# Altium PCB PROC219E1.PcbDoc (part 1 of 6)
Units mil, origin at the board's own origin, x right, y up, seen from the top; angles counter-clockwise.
Board outline 5354.33 x 5354.33 mil, 4 copper layers (Top Layer, Inner Layer 1, Inner Layer 2, Bottom Layer), stack 62.449 mil thick; 579 components, 299 nets, 1709 pads, 802 vias.
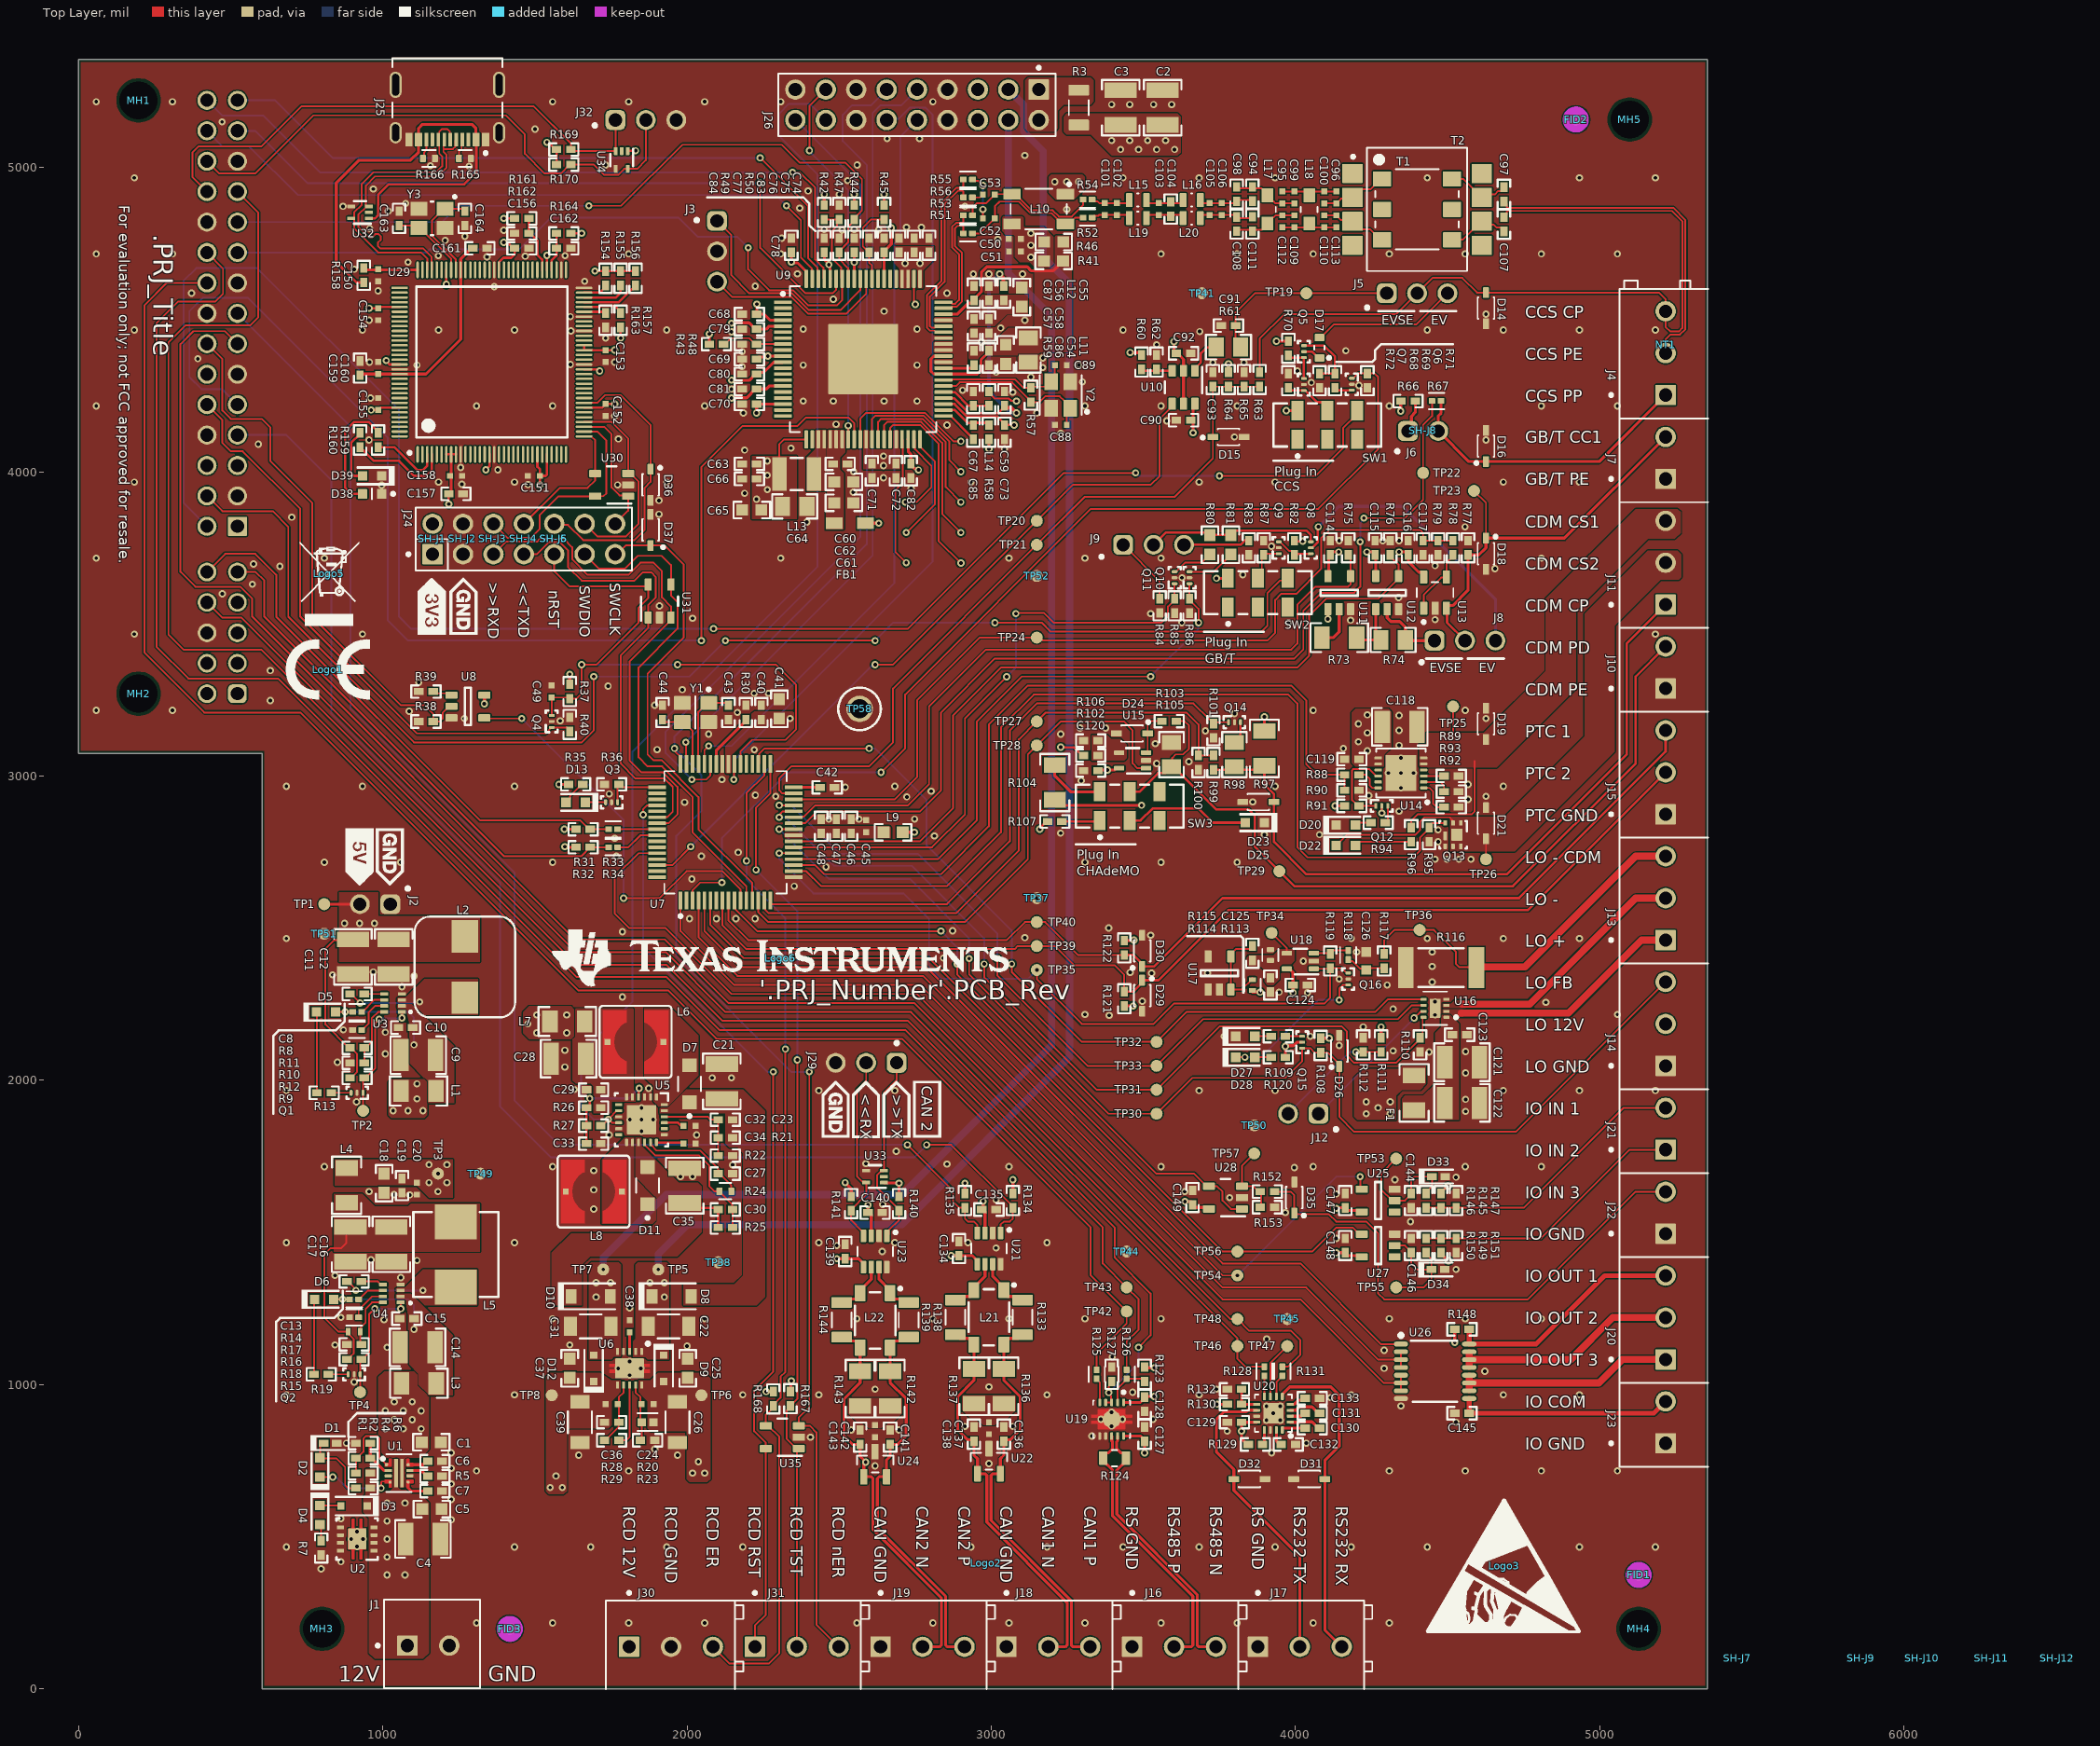
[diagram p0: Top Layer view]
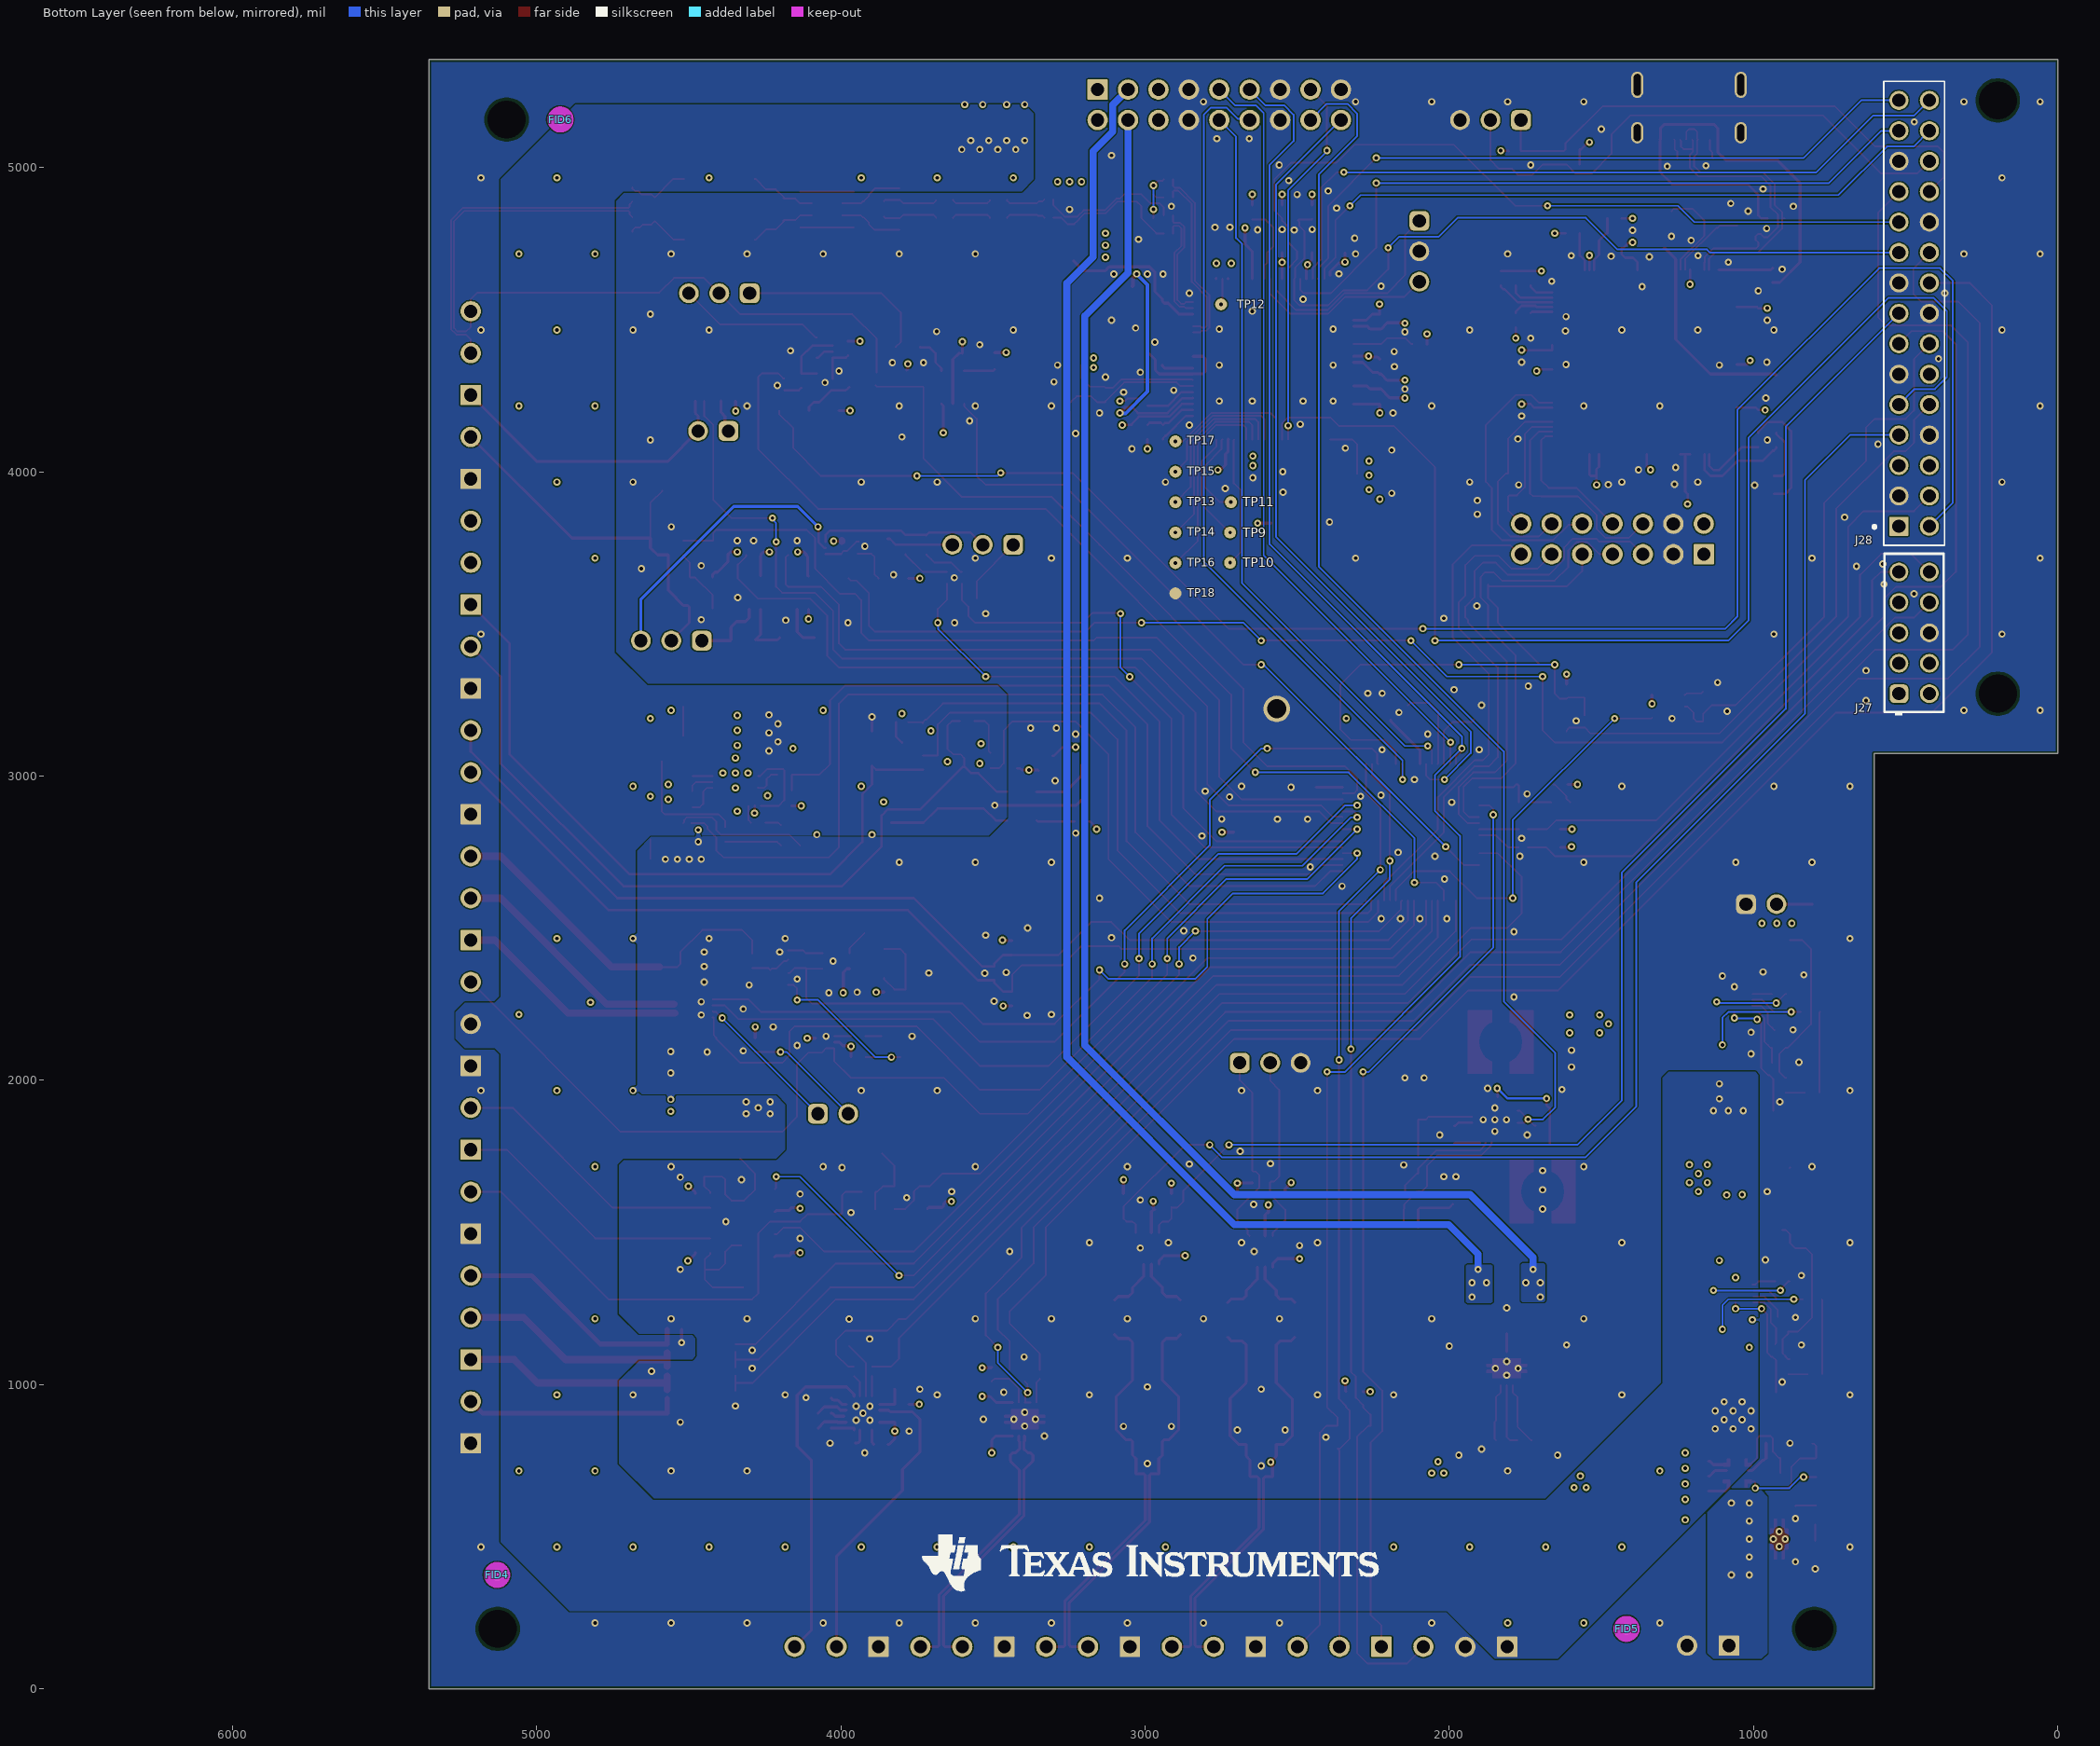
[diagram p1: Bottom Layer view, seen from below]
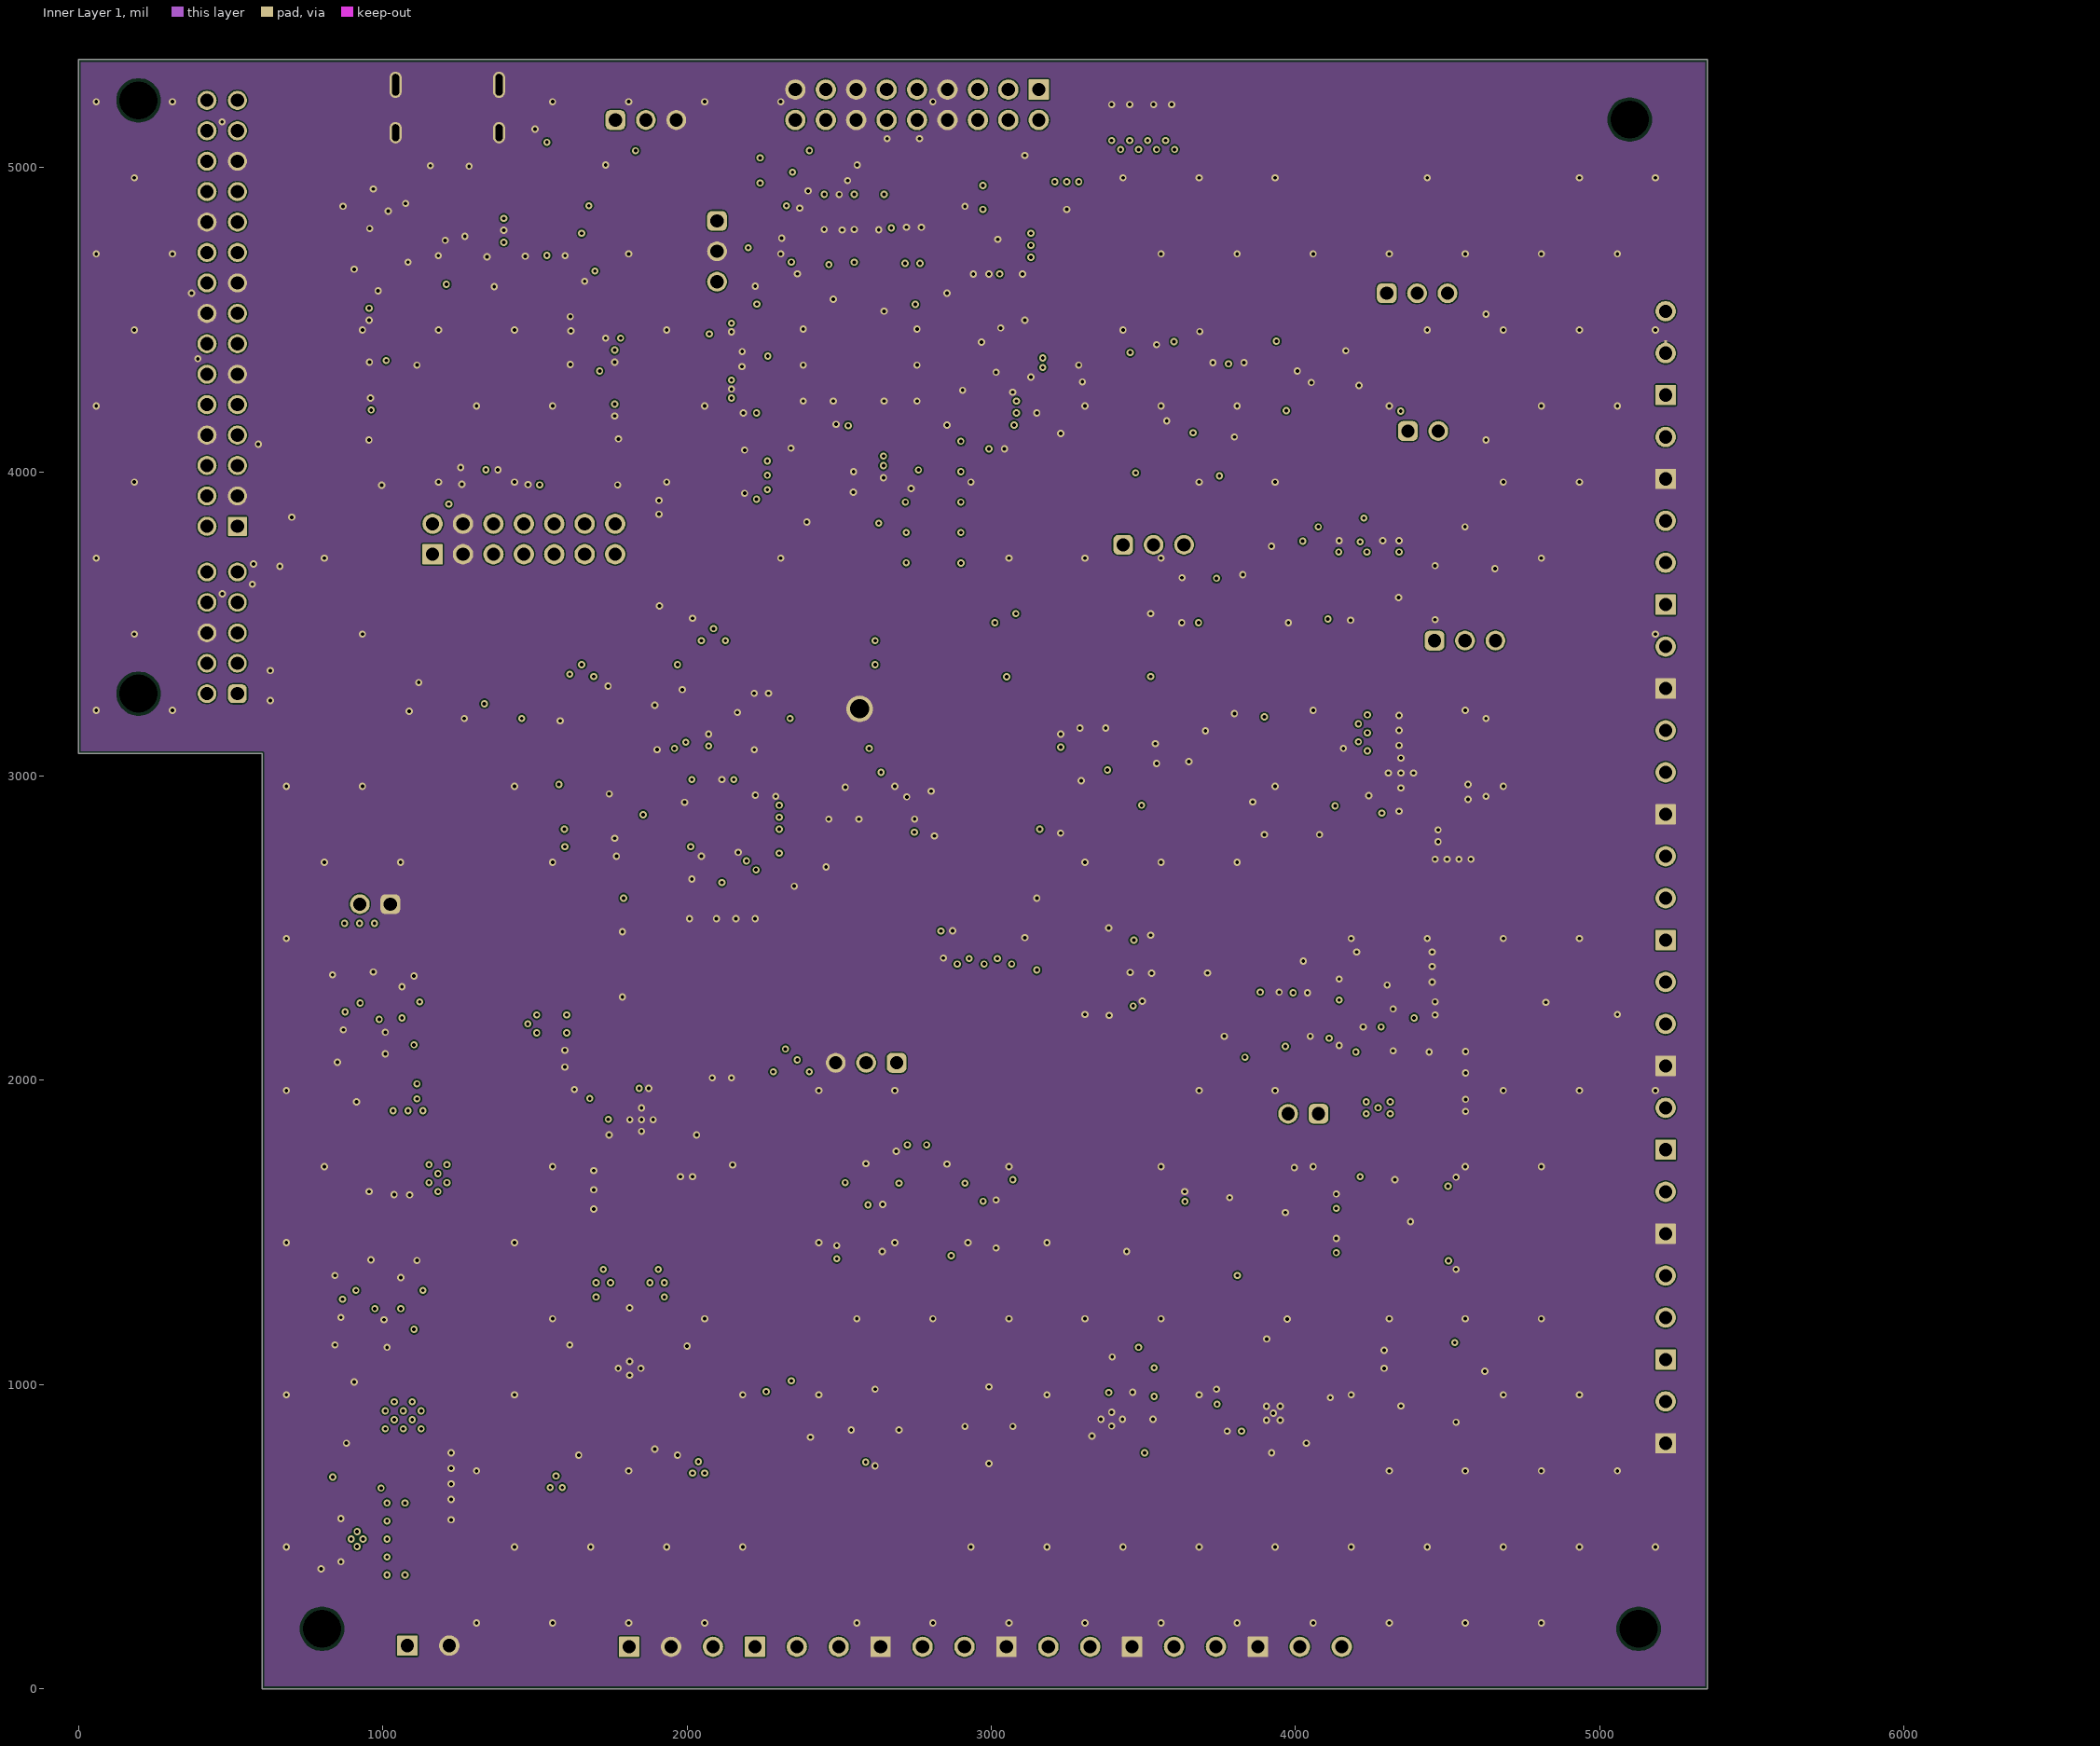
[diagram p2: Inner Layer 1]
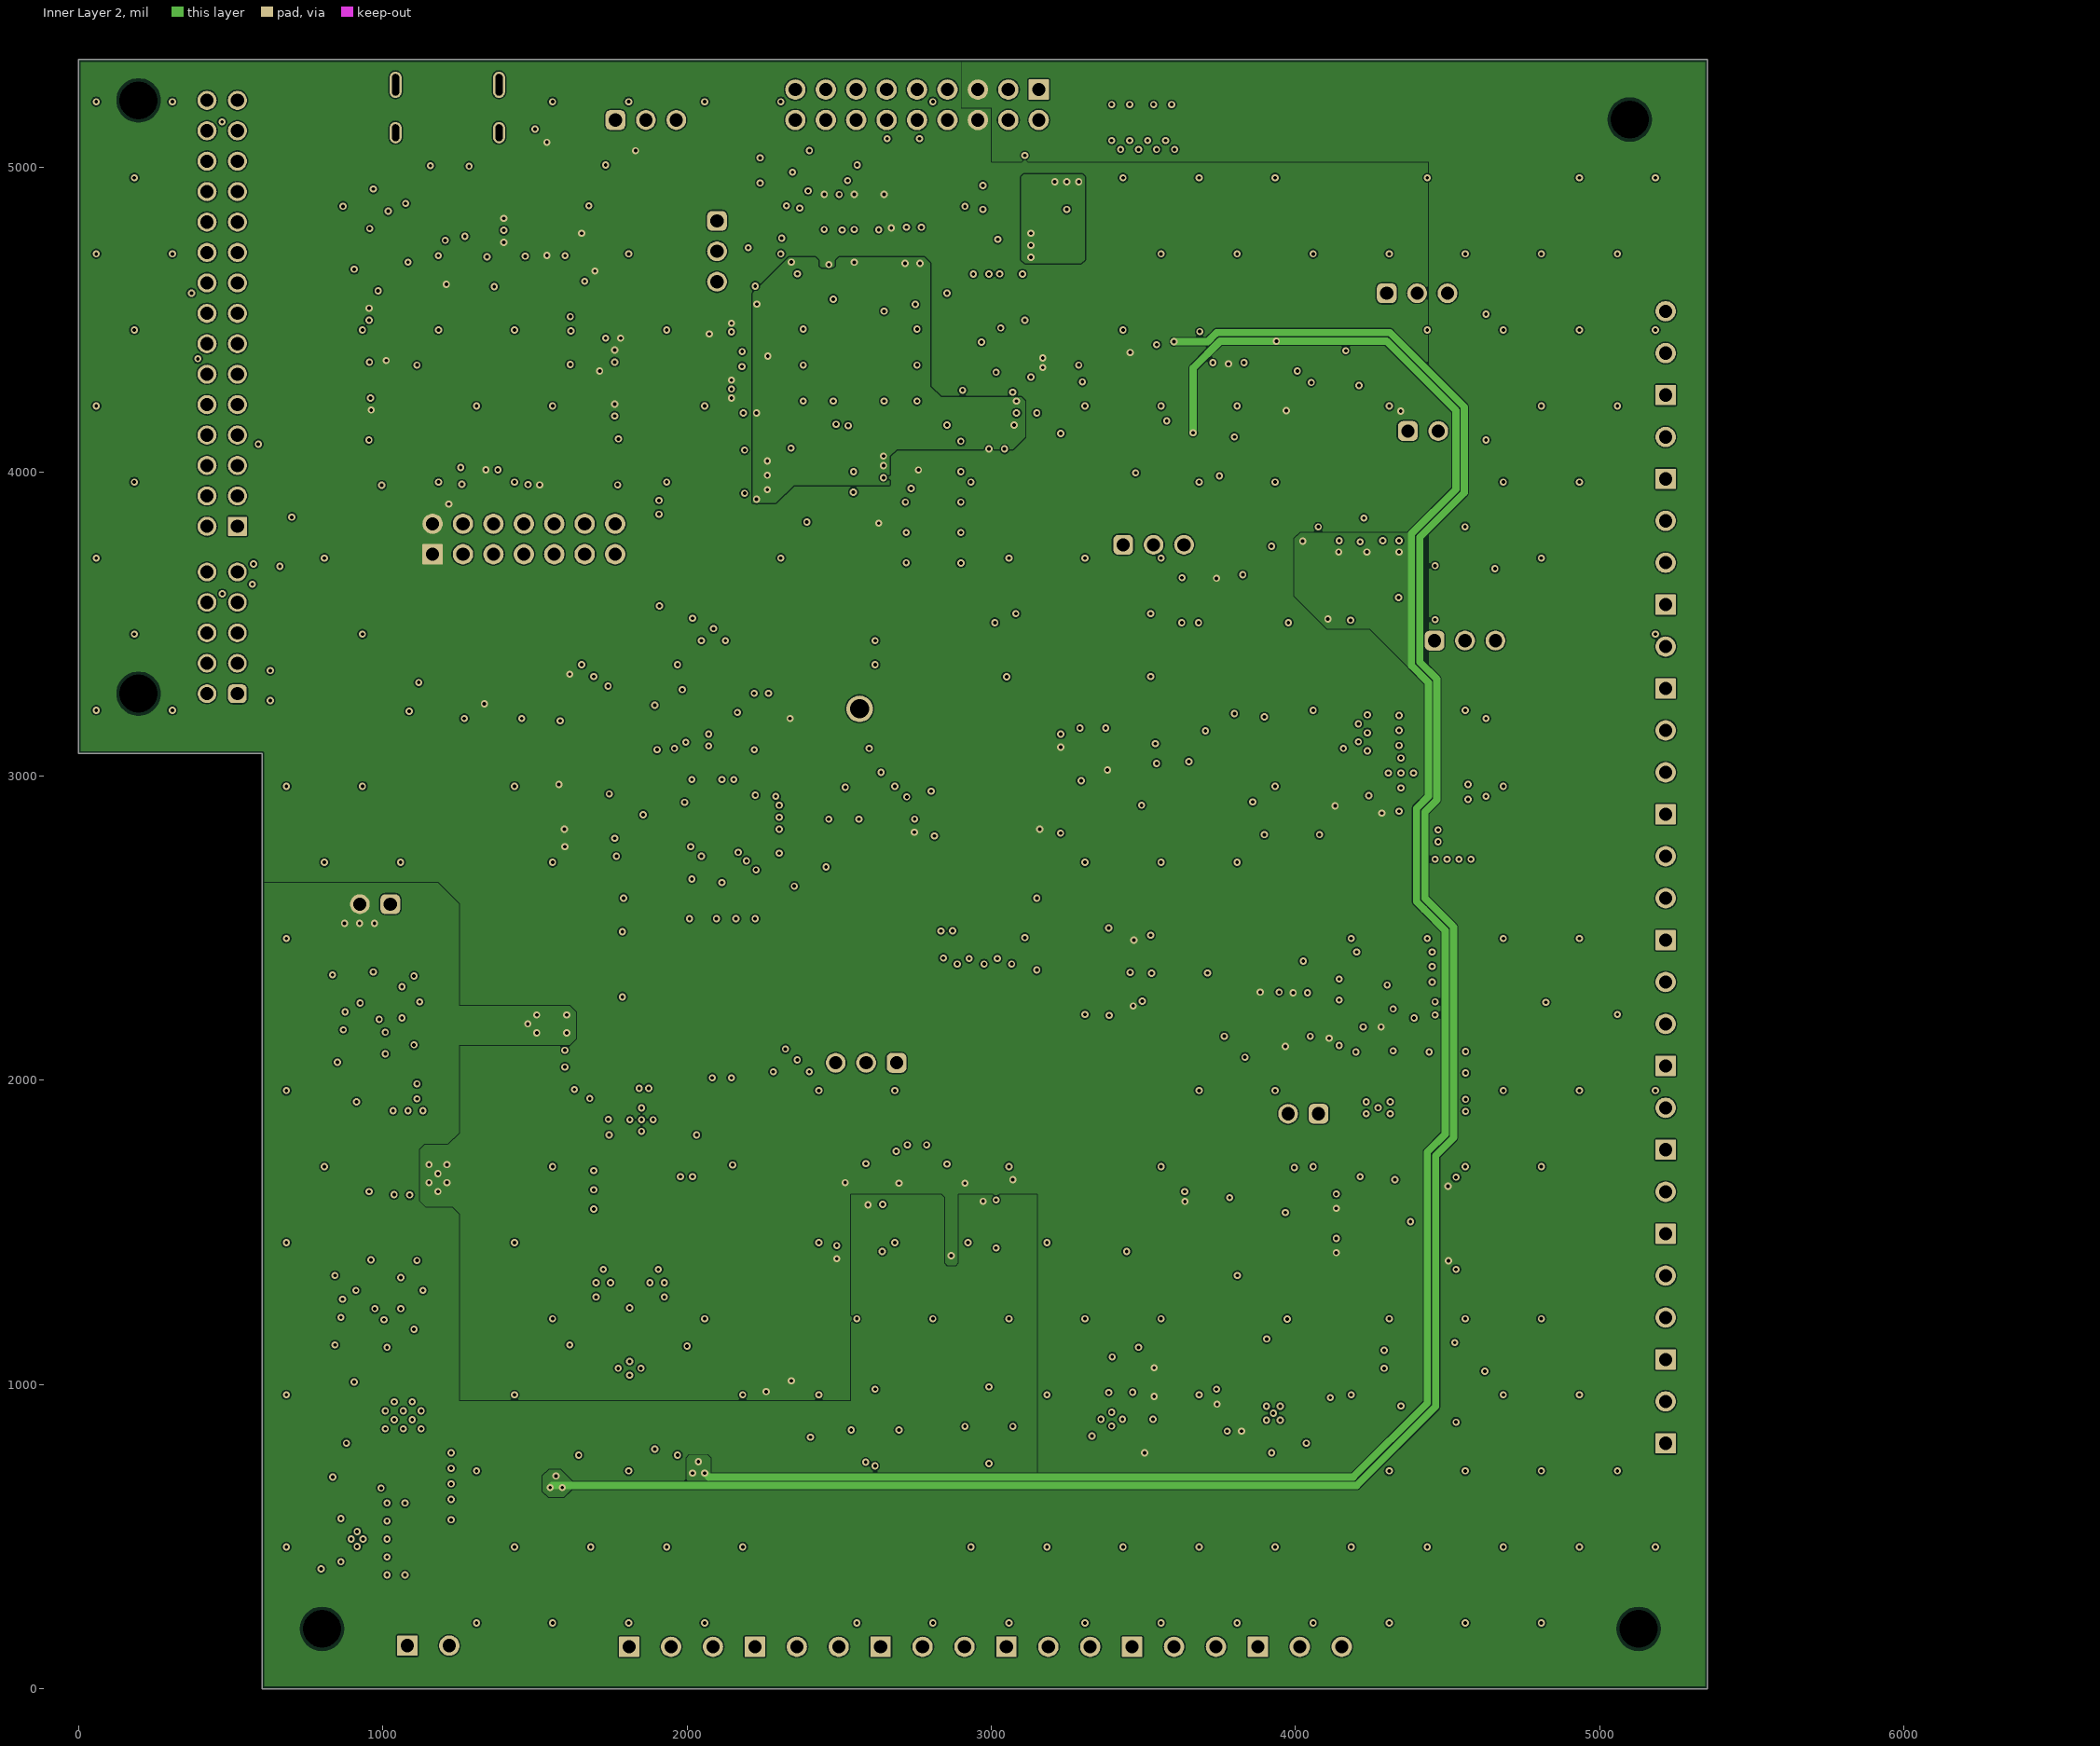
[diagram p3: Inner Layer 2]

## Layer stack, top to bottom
Top Solder: solder mask 0.6, Solder Resist, Dk 3.8
Top Layer: signal copper 1.378
Dielectric 1: prepreg 8.2835, NP-155F, Dk 4.4
Inner Layer 1: signal copper 0.5984
Dielectric 2: core 41.9291, NP-155F, Dk 4.43
Inner Layer 2: signal copper 0.5984
Dielectric 3: prepreg 8.2835, NP-155F, Dk 4.4
Bottom Layer: signal copper 1.378
Bottom Solder: solder mask 0.6, Solder Resist, Dk 3.8

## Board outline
0,3073.62 603.15,3073.62 603.15,0 5354.33,0 5354.33,5354.33 0,5354.33

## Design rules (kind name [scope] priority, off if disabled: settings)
BoardOutlineClearance [All] p1: gap=7.87 ignorepadtopadclearanceinfootprint=FALSE
Clearance [All] p1: gap=4 ignorepadtopadclearanceinfootprint=FALSE except(5: Arc-Via Track-Via SMDPad-Via THPad-Via Via-Via Via-Fill Via-Poly Via-Region Via-Text; 9.84: Arc-Hole Track-Hole SMDPad-Hole THPad-Hole Via-Hole Fill-Hole Poly-Hole Region-Hole Text-Hole)
ComponentClearance T1 [InComponent('T1') vs InComponent('T2')] p1: gap=0 collisioncheckmode=3 verticalgap=0 showdistances=FALSE
ComponentClearance [All] p2: gap=4 collisioncheckmode=3 verticalgap=4 showdistances=TRUE
DiffPairsRouting USB [InDifferentialPair('XDS_USB')] p1: maxlimit=10 minlimit=4 mostfreqgap=7.87 toplayer_minwidth=4 toplayer_maxwidth=15 toplayer_prefwidth=5.91 midlayer1_minwidth=4 midlayer1_maxwidth=15 midlayer1_prefwidth=4 midlayer2_minwidth=4 midlayer2_maxwidth=15 midlayer2_prefwidth=4 bottomlayer_minwidth=4 bottomlayer_maxwidth=15 bottomlayer_prefwidth=4 maxuncoupledlength=500
DiffPairsRouting [All] p2: maxlimit=4 minlimit=4 mostfreqgap=4 toplayer_minwidth=4 toplayer_maxwidth=71497.94 toplayer_prefwidth=4 midlayer1_minwidth=4 midlayer1_maxwidth=71497.94 midlayer1_prefwidth=4 midlayer2_minwidth=4 midlayer2_maxwidth=71497.94 midlayer2_prefwidth=4 bottomlayer_minwidth=4 bottomlayer_maxwidth=71497.94 bottomlayer_prefwidth=4 maxuncoupledlength=500
Height [All] p1: minheight=0 maxheight=71497.94 prefheight=500
HoleSize [All] p1: absolutevalues=TRUE maxlimit=248.03 minlimit=7.87 maxpercent=80.000 minpercent=20.000
HoleToHoleClearance [All] p1: gap=9.84 allowstackedmicrovias=FALSE
MinimumAnnularRing [All] p1: minimumring=3
MinimumSolderMaskSliver [All] p1: minsoldermaskwidth=0
PlaneClearance [All] p1: clearance=4
PlaneConnect PlaneConnectPowerPads [InPadClass('PowerPads')] p1: planeconnectstyle=Direct reliefexpansion=20 reliefentries=4 reliefconductorwidth=10 reliefairgap=10
PlaneConnect [All] p2: pad.planeconnectstyle=Relief pad.reliefexpansion=11.81 pad.reliefentries=4 pad.reliefconductorwidth=4 pad.reliefairgap=4 via.planeconnectstyle=Direct via.reliefexpansion=11.81 via.reliefentries=4 via.reliefconductorwidth=5 via.reliefairgap=5
PolygonConnect PolygonConnectPowerPads [All vs (InPadClass('PowerPads'))] p1: connectstyle=Direct reliefconductorwidth=10 reliefentries=4 polygonreliefangle="90 Angle" airgapwidth=10
PolygonConnect [All] p2: thpad.connectstyle=Relief thpad.reliefconductorwidth=4 thpad.reliefentries=4 thpad.polygonreliefangle="90 Angle" thpad.airgapwidth=4 smdpad.connectstyle=Relief smdpad.reliefconductorwidth=4 smdpad.reliefentries=4 smdpad.polygonreliefangle="90 Angle" smdpad.airgapwidth=4 via.connectstyle=Direct via.reliefconductorwidth=5 via.reliefentries=4 via.polygonreliefangle="90 Angle" via.airgapwidth=5
RoutingVias [All] p1: holewidth=11.81 width=23.62 viastyle="Through Hole" minholewidth=11.81 minwidth=21.65 maxholewidth=248.03 maxwidth=257.87
SilkToBoardRegionClearance [Not ((IsComment or IsDesignator) And (Hide <> 'False')) and not InRegion(1000,500,4000,800)] p1:
SilkToSilkClearance [All] p1: silktosilkclearance=0
SilkToSolderMaskClearance [IsPad] p1: minsilkscreentomaskgap=4 clearancetoexposedcopper=TRUE
SolderMaskExpansion [All] p1: expansion=2.95 istentingtop=FALSE
SupplyNets "Schematic Supply Nets" [InNet('5V')] p1: voltage=0.000
SupplyNets "Schematic Supply Nets_13" [InNet('VCCA_3V3')] p2: voltage=0.000
SupplyNets "Schematic Supply Nets_12" [InNet('3.3V')] p3: voltage=0.000
SupplyNets "Schematic Supply Nets_8" [InNet('GND')] p4: voltage=0.000
SupplyNets "Schematic Supply Nets_7" [InNet('VDD_CORE_1V1')] p5: voltage=0.000
SupplyNets "Schematic Supply Nets_6" [InNet('+12V_EXT')] p6: voltage=0.000
SupplyNets "Schematic Supply Nets_5" [InNet('+12Va')] p7: voltage=0.000
SupplyNets "Schematic Supply Nets_4" [InNet('-14V_EXT')] p8: voltage=0.000
SupplyNets "Schematic Supply Nets_3" [InNet('12V')] p9: voltage=0.000
SupplyNets "Schematic Supply Nets_2" [InNet('+14V_EXT')] p10: voltage=0.000
SupplyNets "Schematic Supply Nets_1" [InNet('-12Va')] p11: voltage=0.000
Width [All] p1: maxlimit=71497.94 minlimit=4 preferedwidth=4
19 further rules are at their usual default settings.

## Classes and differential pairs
component class Shunt: SH-J1 SH-J2 SH-J3 SH-J4 SH-J5 SH-J6 SH-J7 SH-J8 SH-J9 SH-J10 SH-J11 SH-J12
component class PROC219_XDS110_Debug: C150 C151 C152 C153 C154 C155 C156 C157 C158 C159 C160 C161 C162 C163 C164 D36 D37 D38 D39 J24 R154 R155 R156 R157 R158 R159 R160 R161 R162 R163 R164 U29 U30 U31 Y3
component class PROC219_Temp_Sense: D29 D30 J15 R121 R122 TP39 TP40 TP41
component class PROC219_Serial: C127 C128 C129 C130 C131 C132 C133 D31 D32 J16 J17 R123 R124 R125 R126 R127 R128 R129 R130 R131 R132 TP42 TP43 TP44 TP45 TP46 TP47 TP48 U19 U20
component class PROC219_Power_IN_Dig: C1 C2 C3 C4 C5 C6 C7 C8 C9 C10 C11 C12 C13 C14 C15 C16 C17 C18 C19 C20 D1 D2 D3 D4 D5 D6 J1 J2 L1 L2 L3 L4 L5 Q1 Q2 R1 R2 R3 R4 R5 R6 R7 R8 R9 R10 R11 R12 R13 R14 R15 R16 R17 R18 R19 TP1 TP2 TP3 TP4 U1 U2 U3 U4
component class PROC219_Power_Analog: C21 C22 C23 C24 C25 C26 C27 C28 C29 C30 C31 C32 C33 C34 C35 C36 C37 C38 C39 D7 D8 D9 D10 D11 D12 L6 L7 L8 R20 R21 R22 R23 R24 R25 R26 R27 R28 R29 TP5 TP6 TP7 TP8 U5 U6
component class PROC219_PluckLock: C121 C122 C123 C124 C125 C126 D26 D27 D28 F1 J12 J13 J14 Q15 Q16 R108 R109 R110 R111 R112 R113 R114 R115 R116 R117 R118 R119 R120 TP30 TP31 TP32 TP33 TP34 TP35 TP36 TP37 TP38 U16 U17 U18
component class PROC219_PLC: C50 C51 C52 C53 C54 C55 C56 C57 C58 C59 C60 C61 C62 C63 C64 C65 C66 C67 C68 C69 C70 C71 C72 C73 C74 C75 C76 C77 C78 C79 C80 C81 C82 C83 C84 C85 C86 C87 C88 C89 FB1 J3 L10 L11 L12 L13 L14 R41 R42 R43 R44 R45 R46 R47 R48 R49 R50 R51 R52 R53 R54 R55 R56 R57 R58 R59 TP9 TP10 TP11 TP12 TP13 TP14 TP15 TP16 TP17 TP18 U9 Y2
component class PROC219_Pilot_Interface: C90 C91 C92 C93 C94 C95 C96 C97 C98 C99 C100 C101 C102 C103 C104 C105 C106 C107 C108 C109 C110 C111 C112 C113 D14 D15 D16 D17 J4 J5 J6 L15 L16 L17 L18 L19 L20 NT1 Q5 Q6 Q7 R60 R61 R62 R63 R64 R65 R66 R67 R68 R69 R70 R71 R72 SW1 T1 T2 TP19 TP20 TP21 TP22 U10
component class PROC219_MSPM0: C40 C41 C42 C43 C44 C45 C46 C47 C48 C49 D13 L9 Q3 Q4 R30 R31 R32 R33 R34 R35 R36 R37 R38 R39 R40 U7 U8 Y1
component class PROC219_IO: C144 C145 C146 C147 C148 C149 D33 D34 D35 J20 J21 J22 J23 R145 R146 R147 R148 R149 R150 R151 R152 R153 TP53 TP54 TP55 TP56 TP57 U25 U26 U27 U28
component class PROC219_GBT: C114 C115 C116 C117 D18 J7 J8 J9 Q8 Q9 Q10 Q11 R73 R74 R75 R76 R77 R78 R79 R80 R81 R82 R83 R84 R85 R86 R87 SW2 TP23 TP24 U11 U12 U13
component class PROC219_Connectors: J25 J26 J27 J28 J29 J30 J31 J32 R165 R166 R167 R168 R169 R170 U32 U33 U34 U35
component class PROC219_CHAdeMO: C118 C119 C120 D19 D20 D21 D22 D23 D24 D25 J10 J11 Q12 Q13 Q14 R88 R89 R90 R91 R92 R93 R94 R95 R96 R97 R98 R99 R100 R101 R102 R103 R104 R105 R106 R107 SW3 TP25 TP26 TP27 TP28 TP29 U14 U15
component class PROC219_CAN: C134 C135 C136 C137 C138 C139 C140 C141 C142 C143 J18 J19 L21 L22 R133 R134 R135 R136 R137 R138 R139 R140 R141 R142 R143 R144 TP49 TP50 TP51 TP52 U21 U22 U23 U24
component class Header: J2 J3 J5 J6 J8 J9 J12 J29 J32
component class Logo: Logo2 Logo6
component class PROC219_Hardware: FID1 FID2 FID3 FID4 FID5 FID6 Logo1 Logo2 Logo3 Logo4 Logo5 Logo6 MH1 MH2 MH3 MH4 MH5 SH-J1 SH-J2 SH-J3 SH-J4 SH-J5 SH-J6 SH-J7 SH-J8 SH-J9 SH-J10 SH-J11 SH-J12 TP58 ZZ2 ZZ3 ZZ4
component class FiducialMark: FID1 FID2 FID3 FID4 FID5 FID6
component class AssemblyNote: ZZ2 ZZ3 ZZ4
differential pair TX: +TX_P -TX_N
differential pair RX: +RX_P -RX_N
differential pair CP: +CP_P -CP_N
differential pair XDS_USB: +XDS_USB_P -XDS_USB_N
differential pair RS485: +RS485_P -RS485_N
differential pair PLC: +PLC_P -PLC_N
differential pair CAN2: +CAN2_P -CAN2_N
differential pair CAN1: +CAN1_P -CAN1_N

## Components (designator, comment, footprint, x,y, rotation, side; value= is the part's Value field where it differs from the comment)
C1 "C1608X7R1E105K080AB" 0603 1159.28,810.04 r0 top value=1uF
C2 "CC1210KKX7R8BB226" 1210_270 3562.99,5196.85 r270 top value=22uF
C3 "CC1210KKX7R8BB226" 1210_270 3425.2,5196.85 r270 top value=22uF
C4 "CC1210KKX7R8BB226" 1210_270 1131.89,492.13 r180 top value=22uF
C5 "C1608X7R1E105K080AB" 0603 1161.42,590.55 r0 top value=1uF
C6 "CL05B222JB5NNNC" 0402 1171.26,748.03 r0 top value=2200pF
C7 "GRM155R71H332KA01D" 0402 1171.26,649.61 r0 top value=3300pF
C8 "CC0402KRX7R8BB104" 0402 915.35,2283.46 r180 top value=0.1uF
C9 "CC1210KKX7R8BB226" 1210_270 1116.14,2082.68 r0 top value=22uF
C10 "CC0402KRX7R8BB104" 0402 1074.8,2173.23 r180 top value=0.1uF
C11 "CC1210KKX7R8BB226" 1210_270 901.57,2405.51 r90 top value=22uF
C12 "CC1210KKX7R8BB226" 1210_270 1035.43,2405.51 r90 top value=22uF
C13 "CC0402KRX7R8BB104" 0402 905.51,1338.58 r180 top value=0.1uF
C14 "CC1210KKX7R8BB226" 1210_270 1114.17,1122.05 r0 top value=22uF
C15 "CC0402KRX7R8BB104" 0402 1078.74,1216.54 r180 top value=0.1uF
C16 "CC1210KKX7R8BB226" 1210_270 1027.56,1460.63 r90 top value=22uF
C17 "CC1210KKX7R8BB226" 1210_270 893.7,1460.63 r90 top value=22uF
C18 "C1608X7R1E105K080AB" 0603 1003.94,1661.42 r270 top value=1uF
C19 "CC0402KRX7R8BB104" 0402 1062.99,1653.54 r270 top value=0.1uF
C20 "885012205050" WCAP-CSGP_0402_L1W0.5H0.5 1112.2,1643.7 r270 top value=10nF
C21 "CC1210KKX7R8BB226" 1210_270 2114.17,1996.06 r270 top value=22uF
C22 "CL31B106KBHNNNE" 1206_180 1938.98,1190.94 r0 top value=10uF
C23 "GRM1555C1H6R8CA01D" 0402 2125.83,1870.27 r180 top value=6.8pF
C24 "885012205050" WCAP-CSGP_0402_L1W0.5H0.5 1870.08,935.04 r0 top value=10nF
C25 "C1608X7R1E105K080AB" 0603 2001.97,1053.15 r270 top value=1uF
C26 "CL31B106KBHNNNE" 1206_180 1968.5,875.98 r270 top value=10uF
C27 "C1005X7R1C224K050BC" 0402 2125.83,1693.1 r180 top value=0.22uF
C28 "CC1210KKX7R8BB226" 1210_270 1610.24,2070.87 r0 top value=22uF
C29 "CC0402KRX7R8BB104" 0402 1692.76,1968.7 r180 top value=0.1uF
C30 "GRM1555C1H5R6CA01D" 0402 2125.83,1574.99 r0 top value=5.6pF
C31 "CL31B106KBHNNNE" 1206_180 1683.07,1190.94 r180 top value=10uF
C32 "885012205050" WCAP-CSGP_0402_L1W0.5H0.5 2007.72,1850.59 r0 top value=10nF
C33 "CC0402KRX7R8BB104" 0402 1692.76,1791.53 r0 top value=0.1uF
C34 "885012205065" WCAP-CSGP_0402_L1W0.5H0.5 2007.72,1791.53 r0 top value=4.7nF
C35 "CC1210KKX7R8BB226" 1210_270 1992.13,1653.54 r270 top value=22uF
C36 "885012205050" WCAP-CSGP_0402_L1W0.5H0.5 1751.97,935.04 r180 top value=10nF
C37 "C1608X7R1E105K080AB" 0603 1614.17,1053.15 r270 top value=1uF
C38 "885012205050" WCAP-CSGP_0402_L1W0.5H0.5 1811.02,1190.94 r270 top value=10nF
C39 "CL31B106KBHNNNE" 1206_180 1647.64,875.98 r270 top value=10uF
C40 "CC0402KRX7R8BB104" 0402 2244.09,3208.66 r90 top value=0.1uF
C41 "C1608X5R1E106M080AC" 0603 2303.15,3220.47 r90 top value=10uF
C42 "GRM155R60J474KE19D" 0402 2460.63,2962.6 r0 top value=0.47uF
C43 "GRM1555C1H120JA01D" 0402 2135.83,3208.66 r90 top value=12pF
C44 "GRM1555C1H120JA01D" 0402 1919.29,3208.66 r90 top value=12pF
C45 "885012105008" WCAP-CSGP_0402_L1W0.5H0.5 2588.58,2834.65 r270 top value=4.7µF
C46 "CC0402KRX7R8BB104" 0402 2539.37,2834.65 r90 top value=0.1uF
C47 "CC0402KRX7R8BB104" 0402 2490.16,2834.65 r90 top value=0.1uF
C48 "C1005X7S1A105K050BC" 0402 2440.94,2834.65 r270 top value=1uF
C49 "885012205050" WCAP-CSGP_0402_L1W0.5H0.5 1555.12,3277.56 r90 top value=10nF
C50 "885012205061" WCAP-CSGP_0402_L1W0.5H0.5 3077.26,4764.75 r180 top value=1nF
C51 "885012205061" WCAP-CSGP_0402_L1W0.5H0.5 3077.84,4723.93 r180 top value=1nF
C52 "885012205050" WCAP-CSGP_0402_L1W0.5H0.5 2992.13,4832.68 r180 top value=10nF
C53 "885012205050" WCAP-CSGP_0402_L1W0.5H0.5 2992.13,4911.42 r180 top value=10nF
C54 "C1608X5R1E106M080AC" 0603 3047.24,4385.83 r90 top value=10uF
C55 "C1608X5R1E106M080AC" 0603 3100.29,4573.97 r90 top value=10uF
C56 "CC0402KRX7R8BB104" 0402 2992.13,4586.61 r90 top value=0.1uF
C57 "CC0402KRX7R8BB104" 0402 2942.91,4478.35 r270 top value=0.1uF
C58 "CC0402KRX7R8BB104" 0402 2992.13,4478.35 r270 top value=0.1uF
C59 "CC0402KRX7R8BB104" 0402 3043.31,4240.16 r270 top value=0.1uF
C60 "CC0402KRX7R8BB104" 0402 2503.27,4025.59 r0 top value=0.1uF
C61 "C1608X5R1E106M080AC" 0603 2515.25,3897.64 r0 top value=10uF
C62 "C1608X5R1E106M080AC" 0603 2515.25,3966.54 r0 top value=10uF
C63 "CC0402KRX7R8BB104" 0402 2204.72,4025.59 r180 top value=0.1uF
C64 "C2012X7S1A226M125AC" 0805_HV 2353.7,3885.83 r0 top value=22uF
C65 "C1608X5R1E106M080AC" 0603 2212.6,3874.02 r180 top value=10uF
C66 "CC0402KRX7R8BB104" 0402 2204.72,3976.38 r180 top value=0.1uF
C67 "CC0402KRX7R8BB104" 0402 2940.94,4240.16 r90 top value=0.1uF
C68 "CC0402KRX7R8BB104" 0402 2204.72,4517.72 r180 top value=0.1uF
C69 "CC0402KRX7R8BB104" 0402 2204.72,4370.08 r180 top value=0.1uF
C70 "CC0402KRX7R8BB104" 0402 2204.72,4222.44 r180 top value=0.1uF
C71 "CC0402KRX7R8BB104" 0402 2607.45,4003.04 r270 top value=0.1uF
C72 "CC0402KRX7R8BB104" 0402 2686.19,4003.04 r270 top value=0.1uF
C73 "CC0402KRX7R8BB104" 0402 3043.31,4129.92 r270 top value=0.1uF
C74 "CC0402KRX7R8BB104" 0402 2795.28,4744.09 r90 top value=0.1uF
C75 "CC0402KRX7R8BB104" 0402 2746.06,4744.09 r90 top value=0.1uF
C76 "CC0402KRX7R8BB104" 0402 2696.85,4744.09 r90 top value=0.1uF
C77 "CC0402KRX7R8BB104" 0402 2549.21,4744.09 r90 top value=0.1uF
C78 "CC0402KRX7R8BB104" 0402 2342.52,4744.09 r90 top value=0.1uF
C79 "CC0402KRX7R8BB104" 0402 2204.72,4468.5 r180 top value=0.1uF
C80 "CC0402KRX7R8BB104" 0402 2204.72,4320.87 r180 top value=0.1uF
C81 "CC0402KRX7R8BB104" 0402 2204.72,4271.65 r180 top value=0.1uF
C82 "CC0402KRX7R8BB104" 0402 2735.41,4003.04 r270 top value=0.1uF
C83 "CC0402KRX7R8BB104" 0402 2647.64,4744.09 r90 top value=0.1uF
C84 "CC0402KRX7R8BB104" 0402 2450.79,4744.09 r90 top value=0.1uF
C85 "CC0402KRX7R8BB104" 0402 2940.94,4129.92 r90 top value=0.1uF
C86 "CC0402KRX7R8BB104" 0402 2992.13,4374.02 r270 top value=0.1uF
C87 "CC0402KRX7R8BB104" 0402 2942.91,4586.61 r90 top value=0.1uF
C88 "885392005127" WCAP-CSRF_0402_L1W0.5H0.5 3228.35,4153.54 r0 top value=12pF
C89 "885392005127" WCAP-CSRF_0402_L1W0.5H0.5 3228.35,4350.39 r180 top value=12pF
C90 "CC0402KRX7R8BB104" 0402 3631.89,4169.29 r0 top value=0.1uF
C91 "GCM1555C1H301JA16D" 0402 3779.53,4480.31 r180 top value=300pF
C92 "CC0402KRX7R8BB104" 0402 3631.89,4388.97 r180 top value=0.1uF
C93 "04025A101FAT2A" 0402 3728.35,4303.15 r270 top value=100pF
C94 "C1005X5R1C225K050BC" 0402 3858.27,4912.63 r270 top value=2.2uF
C95 "885012005060" WCAP-CSGP_0402_L1W0.5H0.5 3956.69,4901.57 r90 top value=68pF
C96 "885012205060" WCAP-CSGP_0402_L1W0.5H0.5 4133.86,4901.57 r270 top value=680pF
C97 "CL05B272KB5NNNC" 0402 4685.04,4911.42 r90 top value=2700pF
C98 "C1005X7S1A105K050BC" 0402 3806.42,4912.47 r90 top value=1uF
C99 "885012205062" WCAP-CSGP_0402_L1W0.5H0.5 3996.06,4901.57 r90 top value=1.5nF
C100 "885012205063" WCAP-CSGP_0402_L1W0.5H0.5 4094.49,4901.57 r270 top value=2.2nF
C101 "885012005058" WCAP-CSGP_0402_L1W0.5H0.5 3373.35,4863.26 r90 top value=33pF
C102 "885012005058" WCAP-CSGP_0402_L1W0.5H0.5 3412.72,4863.26 r90 top value=33pF
C103 "885392005114" WCAP-CSRF_0402_L1W0.5H0.5 3550.52,4863.26 r90 top value=22pF
C104 "04025A101FAT2A" 0402 3589.89,4863.26 r90 top value=100pF
C105 "885392005116" WCAP-CSRF_0402_L1W0.5H0.5 3717.84,4863.26 r90 top value=27pF
C106 "885012005059" WCAP-CSGP_0402_L1W0.5H0.5 3757.21,4863.26 r90 top value=47pF
C107 "CL05B272KB5NNNC" 0402 4685.04,4812.99 r270 top value=2700pF
C108 "C1005X7S1A105K050BC" 0402 3806.42,4814.04 r270 top value=1uF
C109 "885012205062" WCAP-CSGP_0402_L1W0.5H0.5 3996.06,4822.83 r270 top value=1.5nF
C110 "885012205063" WCAP-CSGP_0402_L1W0.5H0.5 4094.49,4822.83 r90 top value=2.2nF
C111 "C1005X5R1C225K050BC" 0402 3858.27,4814.2 r90 top value=2.2uF
C112 "885012005060" WCAP-CSGP_0402_L1W0.5H0.5 3956.69,4822.83 r270 top value=68pF
C113 "885012205060" WCAP-CSGP_0402_L1W0.5H0.5 4133.86,4822.83 r90 top value=680pF
C114 "CC0402KRX7R8BB104" 0402 4114.17,3750 r270 top value=0.1uF
C115 "CC0402KRX7R8BB104" 0402 4261.81,3750 r270 top value=0.1uF
C116 "CC0402KRX7R8BB104" 0402 4370.08,3750 r90 top value=0.1uF
C117 "04025A101FAT2A" 0402 4419.29,3750 r90 top value=100pF
C118 "CC1210KKX7R8BB226" 1210_270 4342.52,3161.42 r0 top value=22uF
C119 "CC0402KRX7R8BB104" 0402 4185.04,3055.12 r0 top value=0.1uF
C120 "CC0402KRX7R8BB104" 0402 3326.77,3017.72 r180 top value=0.1uF
C121 "CC1210KKX7R8BB226" 1210_270 4547.24,2059.06 r180 top value=22uF
C122 "CC1210KKX7R8BB226" 1210_270 4547.24,1925.2 r180 top value=22uF
C123 "CC0402KRX7R8BB104" 0402 4539.37,2149.61 r0 top value=0.1uF
C124 "CC0402KRX7R8BB104" 0402 4015.75,2312.99 r180 top value=0.1uF
C125 "CC0402KRX7R8BB104" 0402 3917.32,2312.99 r270 top value=0.1uF
C126 "885012206121" WCAP-CSGP_0603_L1.6W0.8H0.8_Reflow 4232.28,2391.73 r270 top value=330nF
C127 "CC0402KRX7R8BB104" 0402 3503.94,836.61 r90 top value=0.1uF
C128 "CC0402KRX7R8BB104" 0402 3503.94,935.04 r270 top value=0.1uF
C129 "CC0402KRX7R8BB104" 0402 3799.21,875.98 r180 top value=0.1uF
C130 "CC0402KRX7R8BB104" 0402 4055.12,856.3 r0 top value=0.1uF
C131 "CC0402KRX7R8BB104" 0402 4055.12,905.51 r0 top value=0.1uF
C132 "CC0402KRX7R8BB104" 0402 3976.38,803.15 r0 top value=0.1uF
C133 "CC0402KRX7R8BB104" 0402 4055.12,954.72 r0 top value=0.1uF
C134 "CC0402KRX7R8BB104" 0402 2893.7,1446.85 r90 top value=0.1uF
C135 "CC0402KRX7R8BB104" 0402 2992.13,1574.8 r0 top value=0.1uF
C136 "C0402C200J5GACTU" 0402 3041.34,836.61 r90 top value=20pF
C137 "885012205065" WCAP-CSGP_0402_L1W0.5H0.5 2992.12,856.3 r270 top value=4.7nF
C138 "C0402C200J5GACTU" 0402 2942.91,836.61 r270 top value=20pF
C139 "CC0402KRX7R8BB104" 0402 2519.68,1437.01 r90 top value=0.1uF
C140 "CC0402KRX7R8BB104" 0402 2618.11,1564.96 r0 top value=0.1uF
C141 "C0402C200J5GACTU" 0402 2667.32,826.77 r90 top value=20pF
C142 "885012205065" WCAP-CSGP_0402_L1W0.5H0.5 2618.11,846.46 r270 top value=4.7nF
C143 "C0402C200J5GACTU" 0402 2568.9,826.77 r270 top value=20pF
C144 "04025A101FAT2A" 0402 4379.92,1604.33 r90 top value=100pF
C145 "CC0402KRX7R8BB104" 0402 4547.24,905.51 r180 top value=0.1uF
C146 "04025A101FAT2A" 0402 4379.92,1456.69 r270 top value=100pF
C147 "CC0402KRX7R8BB104" 0402 4163.39,1604.33 r90 top value=0.1uF
C148 "CC0402KRX7R8BB104" 0402 4163.39,1456.69 r90 top value=0.1uF
C149 "CC0402KRX7R8BB104" 0402 3661.42,1614.17 r90 top value=0.1uF
C150 "885012205050" WCAP-CSGP_0402_L1W0.5H0.5 984.25,4645.67 r90 top value=10nF
C151 "885012205050" WCAP-CSGP_0402_L1W0.5H0.5 1496.06,3986.22 r0 top value=10nF
C152 "885012205050" WCAP-CSGP_0402_L1W0.5H0.5 1732.28,4202.76 r90 top value=10nF
C153 "885012205050" WCAP-CSGP_0402_L1W0.5H0.5 1732.28,4379.92 r90 top value=10nF
C154 "885012205050" WCAP-CSGP_0402_L1W0.5H0.5 984.25,4517.72 r90 top value=10nF
C155 "885012205050" WCAP-CSGP_0402_L1W0.5H0.5 984.25,4222.44 r270 top value=10nF
C156 "C1005X7S1A105K050BC" 0402 1456.69,4734.25 r0 top value=1uF
C157 "C1005X7S1A105K050BC" 0402 1240.16,3927.17 r0 top value=1uF
C158 "885012205050" WCAP-CSGP_0402_L1W0.5H0.5 1240.16,3986.22 r180 top value=10nF
C159 "C1005X7S1A105K050BC" 0402 925.2,4340.55 r90 top value=1uF
C160 "885012205050" WCAP-CSGP_0402_L1W0.5H0.5 984.25,4340.55 r270 top value=10nF
C161 "C1005X7S1A105K050BC" 0402 1318.9,4734.25 r0 top value=1uF
C162 "CC0402KRX7R8BB104" 0402 1594.49,4734.25 r180 top value=0.1uF
C163 "GRM1555C1H120JA01D" 0402 1053.15,4832.68 r90 top value=12pF
C164 "GRM1555C1H120JA01D" 0402 1269.68,4832.68 r270 top value=12pF
D1 "BZT52C5V1T-7" SOD-523 826.77,807.09 r0 top value=5.1V
D2 "150060RS75000" WL-SMCW_RED 793.27,727.42 r90 top value=Red
D3 "BAS20HT1G" SOD-323 905.51,600.39 r180 top value=200V
D4 "150060RS75000" WL-SMCW_RED 793.27,570.87 r270 top value=Red
D5 "150060VS75000" WL-SMCW_GREEN 812.99,2224.41 r0 top value=Green
D6 "150060VS75000" WL-SMCW_GREEN 807.09,1279.53 r0 top value=Green
D7 "SS2040FL_R1_00001" FP-SS2040FL_R1_00001_SOD123FL-MFG 2007.72,1988.38 r90 top
D8 "MBR0540T1G" SOD-123 1948.82,1289.37 r0 top value=40V
D9 "SD103AWS-TP" SOD-323 1923.23,1053.15 r270 top value=40V
D10 "MBR0540T1G" SOD-123 1683.07,1289.37 r0 top value=40V
D11 "SS2040FL_R1_00001" FP-SS2040FL_R1_00001_SOD123FL-MFG 1869.93,1653.73 r90 top
D12 "SD103AWS-TP" SOD-323 1692.91,1053.15 r90 top value=40V
D13 "150060VS75000" WL-SMCW_GREEN 1633.86,2913.39 r180 top value=Green
D14 "TSD12CDYFR" DYF0002A-CA-MFG 4625.98,4537.4 r90 top
D15 "ESDS311DYFR" DYF0002A-MFG 3779.53,4114.17 r0 top
D16 "ESDS311DYFR" DYF0002A-MFG 4625.98,4084.65 r90 top
D17 "RN242SMT2R" FP-RN242SMT2R_EMD2-MFG 4078.74,4407.48 r90 top
D18 "TSD12DYFR" DYF0002A-MFG 4625.98,3730.31 r270 top
D19 "TSD12CDYFR" DYF0002A-CA-MFG 4625.98,3171.26 r270 top
D20 "150060RS75000" WL-SMCW_RED 4165.35,2838.58 r0 top value=Red
D21 "TSD12CDYFR" DYF0002A-CA-MFG 4625.98,2844.49 r270 top
D22 "150060VS75000" WL-SMCW_GREEN 4165.35,2771.65 r0 top value=Green
D23 "TSD12CDYFR" DYF0002A-CA-MFG 3877.95,2914.55 r0 top
D24 "ESDS311DYFR" DYF0002A-MFG 3462.6,3139.76 r180 top
D25 "150060VS75000" WL-SMCW_GREEN 3866.14,2846.46 r180 top value=Green
D26 "ESDS311DYFR" DYF0002A-MFG 4143.7,2096.46 r90 top
D27 "150060VS75000" WL-SMCW_GREEN 3834.84,2144.47 r0 top value=Green
D28 "150060VS75000" WL-SMCW_GREEN 3834.84,2075.57 r0 top value=Green
D29 "ESDS311DYFR" DYF0002A-MFG 3496.06,2277.56 r270 top
D30 "ESDS311DYFR" DYF0002A-MFG 3496.06,2425.2 r90 top
D31 "TSD15C" DYF0002A-CA-MFG 4045.28,688.98 r0 top
D32 "TSD15C" DYF0002A-CA-MFG 3848.43,688.98 r180 top
D33 "BZT52C5V1T-7" SOD-523 4470.14,1683.07 r0 top value=5.1V
D34 "BZT52C5V1T-7" SOD-523 4468.5,1377.95 r0 top value=5.1V
D35 "TSD12DYFR" DYF0002A-MFG 3996.06,1614.17 r90 top
D36 "ESDS311DYFR" DYF0002A-MFG 1879.92,3956.69 r270 top
D37 "ESDS311DYFR" DYF0002A-MFG 1879.92,3809.06 r90 top
D38 "150060AS75000" FP-150060AS75000_0603-MFG 964.57,3927.17 r180 top
D39 "150060VS75000" WL-SMCW_GREEN 964.57,3986.22 r180 top value=Green
F1 "044001.5WR" 1206 4389.76,1958.66 r90 top
FB1 "74279220601" WE-MPSB_0805_L2W1.2H0.9 2535.43,3830.71 r0 top value=600Ω
FID1 "Fiducial" Fiducial10-20 5127.95,374.02 r0 top
FID2 "Fiducial" Fiducial10-20 4921.26,5157.48 r0 top
FID3 "Fiducial" Fiducial10-20 1417.32,196.85 r0 top
FID4 "Fiducial" Fiducial10-20 5129.92,374.02 r180 bottom
FID5 "Fiducial" Fiducial10-20 1417.32,196.85 r180 bottom
FID6 "Fiducial" Fiducial10-20 4921.26,5157.48 r180 bottom
J1 "691214110002S" FP-691214110002S_HDR2-MFG 1161.42,147.64 r0 top
J2 "61300211121" WURTH_61300211121 974.41,2578.74 r180 top
J3 "61300311121" WURTH_61300311121 2098.43,4724.41 r270 top
J4 "691214110003S" FP-691214110003S_CONN_TERM_BLK_3-MFG 5210.63,4389.76 r90 top
J5 "61300311121" WURTH_61300311121 4399.61,4586.61 r0 top
J6 "61300211121" WURTH_61300211121 4419.29,4133.86 r0 top
J7 "691214110002S" FP-691214110002S_HDR2-MFG 5210.63,4057.09 r90 top
J8 "61300311121" WURTH_61300311121 4557.09,3444.88 r0 top
J9 "61300311121" WURTH_61300311121 3533.46,3759.84 r0 top
J10 "691214110002S" FP-691214110002S_HDR2-MFG 5210.63,3368.11 r90 top
J11 "691214110003S" FP-691214110003S_CONN_TERM_BLK_3-MFG 5210.63,3700.79 r90 top
J12 "61300211121" WURTH_61300211121 4025.59,1889.76 r180 top
J13 "691214110003S" FP-691214110003S_CONN_TERM_BLK_3-MFG 5210.63,2598.43 r90 top
J14 "691214110003S" FP-691214110003S_CONN_TERM_BLK_3-MFG 5210.63,2185.04 r90 top
J15 "691214110003S" FP-691214110003S_CONN_TERM_BLK_3-MFG 5210.63,3011.81 r90 top
J16 "691214110003S" FP-691214110003S_CONN_TERM_BLK_3-MFG 3600.79,143.7 r0 top
J17 "691214110003S" FP-691214110003S_CONN_TERM_BLK_3-MFG 4014.17,143.7 r0 top
J18 "691214110003S" FP-691214110003S_CONN_TERM_BLK_3-MFG 3187.4,143.7 r0 top
J19 "691214110003S" FP-691214110003S_CONN_TERM_BLK_3-MFG 2774.02,143.7 r0 top
J20 "691214110003S" FP-691214110003S_CONN_TERM_BLK_3-MFG 5210.63,1219.98 r90 top
J21 "691214110002S" FP-691214110002S_HDR2-MFG 5210.63,1852.36 r90 top
J22 "691214110002S" FP-691214110002S_HDR2-MFG 5210.63,1576.28 r90 top
J23 "691214110002S" FP-691214110002S_HDR2-MFG 5210.63,887.3 r90 top
J24 "61301421121" FP-61301421121_HDR14-MFG 1463.39,3778.74 r0 top
J25 "USB4215-03-A" FP-USB4215-03-A_CONN_USB-MFG 1211.81,5226.38 r180 top
J26 "61301821121" FP-61301821121_HDR18-MFG 2755.91,5205.91 r180 top
J27 "SSW-105-01-G-D" Samtec_SSW-105-01-x-D 471.85,3470.47 r90 bottom
J28 "SSW-115-01-G-D" FP-SSW-115-01-G-D_CONN_RCPT30-MFG 471.85,4520.47 r270 bottom
J29 "61300311121" WURTH_61300311121 2588.58,2057.09 r180 top
J30 "691214110003S" FP-691214110003S_CONN_TERM_BLK_3-MFG 1947.24,143.7 r0 top
J31 "691214110003S" FP-691214110003S_CONN_TERM_BLK_3-MFG 2360.63,143.7 r0 top
J32 "61300311121" WURTH_61300311121 1864.48,5155.91 r0 top
L1 "74279221601" 1206 1117.13,1964.57 r0 top value="600 ohm"
L2 "744311470" WE-HC4 1269.68,2372.05 r90 top value=4.7uH
L3 "74279221601" 1206 1118.11,1003.94 r0 top value="600 ohm"
L4 "74279221281" 1206 880.91,1654.53 r90 top value="280 ohm"
L5 "74437349033" WE-LHMI_7050 1240.16,1427.17 r90 top value=3.3uH
L6 "744042100" WE-TPC-M1 1830.56,2126.18 r0 top value=10uH
L7 "74279221281" 1206 1606.3,2192.91 r0 top value="280 ohm"
L8 "744042100" WE-TPC-M1 1692.76,1634.05 r180 top value=10uH
L9 "742792651" 0603 2677.17,2814.96 r180 top value="600 ohm"
L10 "DLW43SH110XK2L" FP-DLW43SH110XK2L_1812-MFG 3156,4863.17 r180 top
L11 "74279220601" 0805_HV 3122.05,4399.84 r270 top value="600 ohm"
L12 "BLM15AG221SN1D" 0402 3041.34,4586.61 r90 top value="220 ohm"
L13 "74479299222" WE-PMCI_1210_L3.2W2.5H1.2 2360.24,3992.13 r180 top value=2.2uH
L14 "BLM15AG221SN1D" 0402 2992.13,4240.16 r90 top value="220 ohm"
L15 "LQW18ANR27G80D" "FP-LQW18ANR27G80D_0603 (1608)-MFG" 3481.62,4892.78 r0 top value=270nH
L16 "LQW18ANR27G80D" "FP-LQW18ANR27G80D_0603 (1608)-MFG" 3658.79,4892.78 r0 top value=270nH
L17 "LQM21PN4R7MGRD" "FP-LQM21PN4R7MGRD_0805 (2012)-MFG" 3907.48,4862.2 r90 top value=4.7μH
L18 "LQM21PN4R7MGRD" "FP-LQM21PN4R7MGRD_0805 (2012)-MFG" 4045.28,4862.2 r90 top value=4.7μH
L19 "LQW18ANR27G80D" "FP-LQW18ANR27G80D_0603 (1608)-MFG" 3481.62,4833.73 r0 top value=270nH
L20 "LQW18ANR27G80D" "FP-LQW18ANR27G80D_0603 (1608)-MFG" 3658.79,4833.73 r0 top value=270nH
L21 "ACT45B-101-2P-TL003" FP-ACT45B-101-2P-TL003_SMT_4MM5_3MM2-MFG 2992.13,1220.47 r270 top value=100uH
L22 "ACT45B-101-2P-TL003" FP-ACT45B-101-2P-TL003_SMT_4MM5_3MM2-MFG 2618.11,1210.63 r270 top value=100uH
Logo1 "CE Mark" CE_Mark_5mm 818.9,3350.39 r0 top (schematic designator LOGO1)
Logo2 "Texas Instruments" TI_Horizontal_Overlay_Medium 2982.28,413.39 r180 top
Logo3 "ESD Susceptible" ESD_Overlay_Large 4685.04,403.54 r0 top
Logo4 "FCC disclaimer" FCC_disclaimer 25541.34,4094.49 r0 top
Logo5 "WEEE logo" WEEE_Minimum 822.83,3665.35 r0 top
Logo6 "Texas Instruments" TI_Horizontal_Overlay_Medium 2307.09,2401.57 r0 top
MH1 "MTG_NoPads" NPTH125mil#1 196.85,5220.47 r0 top
MH2 "MTG_NoPads" NPTH125mil#1 196.85,3270.47 r0 top
MH3 "MTG_NoPads" NPTH125mil#1 800,196.85 r0 top
MH4 "MTG_NoPads" NPTH125mil#2 5157.48,157.48 r0 top
MH5 "MTG_NoPads" NPTH125mil#3 5157.48,5157.48 r0 top
NT1 "Net-Tie" Net-Tie_10mil 5216.71,4417.35 r270 top net-tie
Q1 "CSD17585F5T" YJK0003A 915.35,1958.66 r180 top value=30V
Q2 "CSD17585F5T" YJK0003A 905.51,1033.46 r180 top value=30V
Q3 "CSD17585F5T" YJK0003A 1751.97,2913.39 r180 top value=30V
Q4 "CSD17585F5T" YJK0003A 1555.12,3179.13 r90 top value=30V
Q5 "CSD25485F5" YJK0003A 4027.56,4394.69 r90 top value=-20V
Q6 "CSD17585F5T" YJK0003A 4185.04,4287.4 r270 top value=30V
Q7 "CSD17585F5T" YJK0003A 4027.56,4286.42 r90 top value=30V
Q8 "CSD25485F5" YJK0003A 4050.42,3750 r90 top value=-20V
Q9 "CSD17585F5T" YJK0003A 3944.88,3750 r90 top value=30V
Q10 "CSD17585F5T" YJK0003A 3651.57,3651.57 r90 top value=30V
Q11 "CSD17585F5T" YJK0003A 3602.36,3651.57 r90 top value=30V
Q12 "CSD25485F5" YJK0003A 4283.46,2901.57 r0 top value=-20V
Q13 "CSD17571Q2" DQK0006C 4517.72,2807.09 r270 top value=30V
Q14 "CSD17585F5T" YJK0003A 3799.21,3176.68 r0 top value=30V
Q15 "CSD25485F5" YJK0003A 4021.85,2124.78 r90 top value=-20V
Q16 "CSD17585F5T" YJK0003A 4173.23,2332.68 r270 top value=30V
R1 "ERJ-2RKF4701X" 0402 935.04,659.45 r0 top value=4.70k
R2 "CRCW0402475KFKED" 0402 935.04,708.66 r0 top value=475k
R3 "CRCW12060000Z0EAC" FP-CRCW12060000Z0EAC_1206-MFG 3287.4,5196.85 r90 top value=0
R4 "CRCW040211K0FKED" 0402 935.04,757.87 r180 top value=11.0k
R5 "CRCW0402750RFKED" 0402 1171.26,698.82 r180 top value=750
R6 "RC0402FR-0747KL" 0402 935.04,807.09 r0 top value=47.0k
R7 "ERJ-2RKF4701X" 0402 797.24,462.6 r270 top value=4.70k
R8 "CRG0402ZR" FP-CRG0402ZR_0402-IPC_C 915.35,2224.41 r180 top value=0
R9 "ERJ-2RKF1002X" 0402 915.35,2007.87 r180 top value=10.0k
R10 "CRCW040273K2FKED" 0402 915.35,2106.3 r180 top value=73.2k
R11 "CRG0402ZR" FP-CRG0402ZR_0402-IPC_C 915.35,2165.35 r180 top value=0
R12 "ERJ-2RKF1002X" 0402 915.35,2057.09 r0 top value=10.0k
R13 "ERJ-2RKF4701X" 0402 807.09,1958.66 r0 top value=4.70k
R14 "CRG0402ZR" FP-CRG0402ZR_0402-IPC_C 905.51,1279.53 r180 top value=0
R15 "ERJ-2RKF1002X" 0402 905.51,1082.68 r180 top value=10.0k
R16 "RC0402FR-0745K3L" 0402S 905.51,1173.23 r180 top value=45.3k
R17 "CRG0402ZR" FP-CRG0402ZR_0402-IPC_C 905.51,1220.47 r180 top value=0
R18 "ERJ-2RKF1002X" 0402 905.51,1131.89 r0 top value=10.0k
R19 "ERJ-2RKF4701X" 0402 797.24,1033.46 r0 top value=4.70k
R20 "RC0402FR-1391KL" FP-RC0402FR-1391KL_0402-IPC_A 1870.08,875.98 r0 top value=91k
R21 "CRCW0402976KFKED" 0402 2125.83,1811.22 r0 top value=976k
R22 "CRCW040293K1FKED" 0402 2125.83,1752.16 r0 top value=93.1k
R23 "ERJ-2RKF1002X" 0402 1870.08,816.93 r0 top value=10.0k
R24 "WR04X6802FTL" FP-WR04X6802FTL_0402-MFG 2125.83,1635.03 r0 top value=68k
R25 "CRCW0402787KFKED" 0402 2125.83,1515.94 r180 top value=787k
R26 "ERJ-2RKF1000X" 0402 1692.76,1909.64 r0 top value=100
R27 "ERJ-2RKF1002X" 0402 1692.76,1850.59 r180 top value=10.0k
R28 "RC0402FR-07100KL" 0402 1751.97,875.98 r180 top value=100k
R29 "ERJ-2RKF1002X" 0402 1751.97,816.93 r0 top value=10.0k
R30 "RC0402FR-07100KL" 0402 2192.91,3208.66 r270 top value=100k
R31 "ERJ-2RKF1002X" 0402 1658.42,2824.8 r180 top value=10.0k
R32 "ERJ-2RKF1002X" 0402 1658.42,2765.75 r180 top value=10.0k
R33 "CRG0402ZR" FP-CRG0402ZR_0402-IPC_C 1756.84,2824.8 r180 top value=0
R34 "CRG0402ZR" FP-CRG0402ZR_0402-IPC_C 1756.84,2765.75 r180 top value=0
R35 "CRCW0402220RJNED" 0402 1633.86,2972.44 r180 top value=220
R36 "ERJ-2RKF1002X" 0402 1751.97,2972.44 r180 top value=10.0k
R37 "RC0402FR-0747KL" 0402 1614.17,3277.56 r90 top value=47.0k
R38 "ERJ-2RKF1002X" 0402 1141.73,3179.13 r0 top value=10.0k
R39 "ERJ-2RKF1002X" 0402 1141.73,3277.56 r0 top value=10.0k
R40 "ERJ-2RKF1002X" 0402 1614.17,3169.29 r90 top value=10.0k
R41 "RC0603FR-0710RL" 0603 3204.72,4692.91 r180 top value=10.0
R42 "ERJ-2RKF4701X" 0402 2450.79,4852.36 r90 top value=4.70k
R43 "ERJ-2RKF4701X" 0402 2096.46,4419.29 r180 top value=4.70k
R44 "ERJ-2RKF4701X" 0402 2549.21,4852.36 r90 top value=4.70k
R45 "ERJ-2RKF4701X" 0402 2647.64,4852.36 r90 top value=4.70k
R46 "RC0603FR-0710RL" 0603 3205.21,4754.91 r180 top value=10.0
R47 "ERJ-2RKF4701X" 0402 2500,4852.36 r270 top value=4.70k
R48 "ERJ-2RKF4701X" 0402 2204.72,4419.29 r0 top value=4.70k
R49 "ERJ-2RKF4701X" 0402 2500,4744.09 r270 top value=4.70k
R50 "ERJ-2RKF4701X" 0402 2598.43,4744.09 r270 top value=4.70k
R51 "CRG0402ZR" FP-CRG0402ZR_0402-IPC_C 2923.23,4783.46 r180 top value=0
R52 "CRG0402ZR" FP-CRG0402ZR_0402-IPC_C 3316.46,4835.5 r180 top value=0
R53 "CRG0402ZR" FP-CRG0402ZR_0402-IPC_C 2923.23,4842.52 r180 top value=0
R54 "CRG0402ZR" FP-CRG0402ZR_0402-IPC_C 3316.46,4894.56 r180 top value=0
R55 "CRG0402ZR" FP-CRG0402ZR_0402-IPC_C 2923.23,4960.63 r180 top value=0
R56 "CRG0402ZR" FP-CRG0402ZR_0402-IPC_C 2923.23,4901.57 r180 top value=0
R57 "RC0402FR-071ML" 0402 3129.92,4251.97 r90 top value=1.00Meg
R58 "ERJ-2RKF1000X" 0402 2992.13,4129.92 r270 top value=100
R59 "CRCW04025K76FKED" 0402 2942.91,4374.02 r270 top value=5.76k
R60 "ERJ-2RKF2003X" 0402 3494.09,4360.24 r90 top value=200k
R61 "RP73PF2A1K0BTDF" 0805_HV 3779.53,4409.45 r0 top value=1.00k
R62 "ERJ-2RKF2003X" 0402 3543.31,4360.24 r270 top value=200k
R63 "ERJ-2RKF2003X" 0402 3881.89,4303.15 r90 top value=200k
R64 "CRCW040254K9FKED" 0402 3779.53,4303.15 r90 top value=54.9k
R65 "CRCW040263K4FKED" 0402 3830.71,4303.15 r270 top value=63.4k
R66 "RC0402FR-071KL" 0402 4370.08,4232.28 r180 top value=1.00k
R67 "CRG0402ZR" FP-CRG0402ZR_0402-IPC_C 4463.53,4232.28 r180 top value=0
R68 "CRCW04022K74FKED" 0402 4078.74,4299.21 r90 top value=2.74k
R69 "CRCW04021K30FKED" 0402 4129.92,4299.21 r90 top value=1.30k
R70 "ERJ-2RKF1002X" 0402 3976.38,4405.51 r270 top value=10.0k
R71 "ERJ-2RKF1002X" 0402 4236.22,4299.21 r270 top value=10.0k
R72 "ERJ-2RKF1002X" 0402 3976.38,4299.21 r90 top value=10.0k
R73 "RP73D2B1K0BTG" 1206 4143.7,3454.72 r0 top value=1.00k
R74 "RT0805BRD0710KL" 0805_HV 4320.87,3447.09 r0 top value=10.0k
R75 "ERJ-2RKF1002X" 0402 4173.23,3750 r270 top value=10.0k
R76 "ERJ-2RKF1002X" 0402 4311.02,3750 r270 top value=10.0k
R77 "RC0402FR-071ML" 0402 4566.93,3750 r90 top value=1.00Meg
R78 "ERJ-2RKF1002X" 0402 4517.72,3750 r270 top value=10.0k
R79 "CRCW04023K60JNED" 0402 4468.5,3750 r90 top value=3.6k
R80 "RT0603BRD072K74L" 0603 3718.5,3759.84 r90 top value=2.74k
R81 "RT0603BRD071K3L" 0603 3787.4,3759.84 r90 top value=1.30k
R82 "ERJ-2RKF1002X" 0402 3996.06,3750 r270 top value=10.0k
R83 "RC0402FR-071KL" 0402 3846.46,3750 r90 top value=1.00k
R84 "RC0402FR-07100KL" 0402 3553.45,3559.28 r90 top value=100k
R85 "ERJ-2RKF1002X" 0402 3602.36,3559.06 r270 top value=10.0k
R86 "ERJ-2RKF1002X" 0402 3651.57,3559.06 r270 top value=10.0k
R87 "ERJ-2RKF1002X" 0402 3895.67,3750 r90 top value=10.0k
R88 "ERJ-2RKF1002X" 0402 4185.04,3003.94 r0 top value=10.0k
R89 "CRCW040214K7FKED" 0402 4511.81,3000 r180 top value=14.7k
R90 "ERJ-2RKF1002X" 0402 4185.04,2952.76 r0 top value=10.0k
R91 "ERJ-2RKF1002X" 0402 4185.04,2901.57 r0 top value=10.0k
R92 "ERJ-2RKF1002X" 0402 4511.81,2897.64 r180 top value=10.0k
R93 "ERJ-2RKF1002X" 0402 4511.81,2948.82 r180 top value=10.0k
R94 "CRCW0402220RJNED" 0402 4271.65,2846.46 r0 top value=220
R95 "ERJ-2RKF1002X" 0402 4438.98,2807.09 r90 top value=10.0k
R96 "ERJ-2RKF4701X" 0402 4379.92,2807.09 r270 top value=4.70k
R97 "RP73D2B1K0BTG" 1206 3897.64,3090.55 r270 top value=1.00k
R98 "RT0805BRD07200RL" 0805_HV 3799.21,3070.06 r270 top value=200
R99 "ERJ-2RKF1002X" 0402 3730.31,3044.06 r90 top value=10.0k
R100 "CRCW04023K60JNED" 0402 3681.1,3044.06 r90 top value=3.6k
R101 "ERJ-2RKF1002X" 0402 3730.31,3148.8 r270 top value=10.0k
R102 "RC0402FR-07100KL" 0402 3326.77,3066.93 r180 top value=100k
R103 "ERJ-2RKF1002X" 0402 3584.52,3179.92 r180 top value=10.0k
R104 "RP73D2B1K0BTG" 1206 3208.66,2978.35 r90 top value=1.00k
R105 "RT0805BRD07200RL" 0805_HV 3592.52,3070.06 r270 top value=200
R106 "CRCW040254K9FKED" 0402 3326.77,3116.14 r0 top value=54.9k
R107 "CRCW0402220RJNED" 0402 3208.66,2850.39 r180 top value=220
R108 "RC0402FR-071KL" 0402 4082.68,2114.17 r90 top value=1.00k
R109 "CRCW0402220RJNED" 0402 3943.11,2144.47 r0 top value=220
R110 "ERJ-2RKF1002X" 0402 4409.45,2116.14 r270 top value=10.0k
R111 "ERJ-2RKF1002X" 0402 4281.5,2116.14 r270 top value=10.0k
R112 "ERJ-2RKF1002X" 0402 4222.44,2116.14 r90 top value=10.0k
R113 "TNPW0402150RBEED" FP-TNPW0402150RBEED_0402-MFG 3858.27,2312.99 r270 top value=150
R114 "CRCW040225K5FKED" 0402 3858.27,2417.32 r270 top value=25.5k
R115 "TNPW0402150RBEED" FP-TNPW0402150RBEED_0402-MFG 3917.32,2411.42 r270 top value=150
R116 "CSRN2512FKR500" 2512 4478.35,2370.08 r180 top value=0.5
R117 "RC0402FR-071KL" 0402 4291.34,2391.73 r90 top value=1.00k
R118 "CRG0402ZR" FP-CRG0402ZR_0402-IPC_C 4173.23,2411.42 r270 top value=0
R119 "RC0402FR-071ML" 0402 4114.17,2391.73 r270 top value=1.00Meg
R120 "CRCW0402220RJNED" 0402 3943.11,2075.57 r0 top value=220
R121 "RT0402BRD0710KL" 0402 3437.01,2267.72 r270 top value=10.0k
R122 "RT0402BRD0710KL" 0402 3437.01,2435.04 r90 top value=10.0k
R123 "ERJ-2RKF4701X" 0402 3503.94,1033.46 r90 top value=4.70k
R124 "SDR10EZPF1200" FP-SDR10EZPF1200_0805-MFG 3405.51,757.87 r180 top value=120
R125 "CRG0402ZR" FP-CRG0402ZR_0402-IPC_C 3346.46,1033.46 r90 top value=0
R126 "CRG0402ZR" FP-CRG0402ZR_0402-IPC_C 3444.88,1033.46 r90 top value=0
R127 "ERJ-2RKF4701X" 0402 3395.67,1033.46 r270 top value=4.70k
R128 "CRG0402ZR" FP-CRG0402ZR_0402-IPC_C 3897.64,1043.31 r90 top value=0
R129 "ERJ-2RKF1002X" 0402 3868.11,803.15 r180 top value=10.0k
R130 "ERJ-2RKF1002X" 0402 3799.21,935.04 r0 top value=10.0k
R131 "CRG0402ZR" FP-CRG0402ZR_0402-IPC_C 3956.69,1043.31 r90 top value=0
R132 "ERJ-2RKF1002X" 0402 3799.21,984.25 r180 top value=10.0k
R133 "CRCW12060000Z0EAC" FP-CRCW12060000Z0EAC_1206-MFG 3102.36,1220.47 r270 top value=0
R134 "ERJ-2RKF4701X" 0402 3070.87,1604.33 r90 top value=4.70k
R135 "ERJ-2RKF4701X" 0402 2913.39,1604.33 r90 top value=4.70k
R136 "CRCW120659R0FKEA" 1206 3041.34,994.09 r90 top value=59.0
R137 "CRCW120659R0FKEA" 1206 2942.91,994.09 r270 top value=59.0
R138 "CRCW12060000Z0EAC" FP-CRCW12060000Z0EAC_1206-MFG 2881.89,1220.47 r270 top value=0
R139 "CRCW12060000Z0EAC" FP-CRCW12060000Z0EAC_1206-MFG 2728.35,1212.6 r270 top value=0
R140 "ERJ-2RKF4701X" 0402 2696.85,1594.49 r90 top value=4.70k
R141 "ERJ-2RKF4701X" 0402 2539.37,1594.49 r90 top value=4.70k
R142 "CRCW120659R0FKEA" 1206 2667.32,986.22 r90 top value=59.0
R143 "CRCW120659R0FKEA" 1206 2568.9,986.22 r270 top value=59.0
R144 "CRCW12060000Z0EAC" FP-CRCW12060000Z0EAC_1206-MFG 2507.87,1212.6 r270 top value=0
R145 "ERJ-2RKF1002X" 0402 4478.35,1604.33 r270 top value=10.0k
R146 "ERJ-2RKF1002X" 0402 4429.13,1604.33 r90 top value=10.0k
R147 "ERJ-2RKF1002X" 0402 4527.56,1604.33 r270 top value=10.0k
R148 "ERJ-2RKF4701X" 0402 4547.24,1181.1 r180 top value=4.70k
R149 "ERJ-2RKF1002X" 0402 4478.35,1456.69 r90 top value=10.0k
R150 "ERJ-2RKF1002X" 0402 4429.13,1456.69 r270 top value=10.0k
R151 "ERJ-2RKF1002X" 0402 4527.56,1456.69 r90 top value=10.0k
R152 "RT0402BRD0710KL" 0402 3907.48,1633.86 r0 top value=10.0k
R153 "CRCW04023K32FKED" 0402 3907.48,1582.68 r180 top value=3.32k
R154 "RC0402FR-071KL" 0402 1732.28,4635.83 r90 top value=1.00k
R155 "RC0402FR-071KL" 0402 1781.5,4635.83 r90 top value=1.00k
R156 "RC0402FR-071KL" 0402 1830.71,4635.83 r90 top value=1.00k
R157 "RC0402FR-071KL" 0402 1781.5,4498.03 r270 top value=1.00k
R158 "ERJ-2RKF1000X" 0402 937.01,4645.67 r90 top value=100
R159 "RC0402FR-07470RL" 0402 984.25,4104.33 r270 top value=470
R160 "RC0402FR-07470RL" 0402 925.2,4104.33 r270 top value=470
R161 "ERJ-2RKF1002X" 0402 1456.69,4832.68 r180 top value=10.0k
R162 "ERJ-2RKF1002X" 0402 1456.69,4783.46 r0 top value=10.0k
R163 "CRCW04024K87FKED" 0402 1732.28,4498.03 r90 top value=4.87k
R164 "CRCW040251R0JNED" 0402 1594.49,4783.46 r0 top value=51
R165 "RMCF0402FT5K10" FP-RMCF0402FT5K10_0402-MFG 1269.68,5029.53 r180 top value=5.1k
R166 "RMCF0402FT5K10" FP-RMCF0402FT5K10_0402-MFG 1151.57,5029.53 r180 top value=5.1k
R167 "ERJ-2RKF4701X" 0402 2339.65,953.3 r90 top value=4.70k
R168 "ERJ-2RKF4701X" 0402 2283.46,952.76 r90 top value=4.70k
R169 "ERJ-2RKF4701X" 0402 1594.49,5059.06 r180 top value=4.70k
R170 "ERJ-2RKF4701X" 0402 1594.49,5009.84 r180 top value=4.70k
SH-J1 "60900213421" Wurth_60900213421 1162.2,3779.53 r90 top
SH-J2 "60900213421" Wurth_60900213421 1262.2,3779.53 r90 top
SH-J3 "60900213421" Wurth_60900213421 1362.2,3779.53 r90 top
SH-J4 "60900213421" Wurth_60900213421 1462.2,3779.53 r90 top
SH-J5 "60900213421" Wurth_60900213421 1562.2,3779.53 r90 top
SH-J6 "60900213421" Wurth_60900213421 1562.2,3779.53 r90 top
SH-J7 "60900213421" Wurth_60900213421 5453.66,99.86 r90 top
SH-J8 "60900213421" Wurth_60900213421 4419.29,4135.04 r90 top
SH-J9 "60900213421" Wurth_60900213421 5859.17,99.86 r90 top
SH-J10 "60900213421" Wurth_60900213421 6059.95,99.86 r90 top
SH-J11 "60900213421" Wurth_60900213421 6288.3,99.86 r90 top
SH-J12 "60900213421" Wurth_60900213421 6504.84,99.86 r90 top
SW1 "JS202011JCQN" FP-JS202011JCQN-MFG 4104.33,4153.54 r0 top
SW2 "JS202011JCQN" FP-JS202011JCQN-MFG 3875.98,3602.36 r0 top
SW3 "JS202011JCQN" FP-JS202011JCQN-MFG 3454.72,2900.77 r0 top
T1 "PWB3010LC" FP-PWB3010LC_SMD6-MFG 4399.61,4862.2 r0 top
T2 "ZA9756-AED" FP-ZA9756-AED_SMD8-MFG 4399.61,4862.2 r0 top value=215µH
TP1 "TP_SM_1MM" TP_SM_1MM 807.09,2578.74 r90 top
TP2 "TP_SM_1MM" TP_SM_1MM 935.04,1899.61 r90 top
TP3 "TP_SM_1MM" TP_SM_1MM 1181.1,1692.91 r90 top
TP4 "TP_SM_1MM" TP_SM_1MM 925.2,974.41 r90 top
TP5 "TP_SM_1MM" TP_SM_1MM 1905.51,1377.95 r0 top
TP6 "TP_SM_1MM" TP_SM_1MM 2047.24,964.57 r90 top
TP7 "TP_SM_1MM" TP_SM_1MM 1724.41,1377.95 r0 top
TP8 "TP_SM_1MM" TP_SM_1MM 1555.12,964.57 r270 top
TP9 "TP_SM_1MM" TP_SM_1MM 2720.47,3800 r180 bottom
TP10 "TP_SM_1MM" TP_SM_1MM 2720.47,3700.79 r90 bottom
TP11 "TP_SM_1MM" TP_SM_1MM 2717.67,3900 r180 bottom
TP12 "TP_SM_1MM" TP_SM_1MM 2750,4550 r90 bottom
TP13 "TP_SM_1MM" TP_SM_1MM 2900,3900 r180 bottom
TP14 "TP_SM_1MM" TP_SM_1MM 2900,3800 r180 bottom
TP15 "TP_SM_1MM" TP_SM_1MM 2900,4000 r180 bottom
TP16 "TP_SM_1MM" TP_SM_1MM 2900,3700 r180 bottom
TP17 "TP_SM_1MM" TP_SM_1MM 2900,4100 r270 bottom
TP18 "TP_SM_1MM" TP_SM_1MM 2900,3600 r270 bottom
TP19 "TP_SM_1MM" TP_SM_1MM 4035.43,4586.61 r90 top
TP20 "TP_SM_1MM" TP_SM_1MM 3149.61,3838.58 r270 top
TP21 "TP_SM_1MM" TP_SM_1MM 3149.61,3759.84 r180 top
TP22 "TP_SM_1MM" TP_SM_1MM 4419.29,3996.06 r180 top
TP23 "TP_SM_1MM" TP_SM_1MM 4586.61,3937.01 r180 top
TP24 "TP_SM_1MM" TP_SM_1MM 3149.61,3454.72 r90 top
TP25 "TP_SM_1MM" TP_SM_1MM 4517.72,3228.35 r0 top
TP26 "TP_SM_1MM" TP_SM_1MM 4625.98,2726.38 r270 top
TP27 "TP_SM_1MM" TP_SM_1MM 3149.61,3179.13 r90 top
TP28 "TP_SM_1MM" TP_SM_1MM 3149.61,3100.39 r270 top
TP29 "TP_SM_1MM" TP_SM_1MM 3946.85,2687.01 r90 top
TP30 "TP_SM_1MM" TP_SM_1MM 3543.31,1889.76 r90 top
TP31 "TP_SM_1MM" TP_SM_1MM 3543.31,1968.5 r180 top
TP32 "TP_SM_1MM" TP_SM_1MM 3543.31,2125.98 r90 top
TP33 "TP_SM_1MM" TP_SM_1MM 3543.31,2047.24 r90 top
TP34 "TP_SM_1MM" TP_SM_1MM 3921.26,2484.25 r90 top
TP35 "TP_SM_1MM" TP_SM_1MM 3149.61,2362.2 r270 top
TP36 "TP_SM_1MM" TP_SM_1MM 4408.09,2493.95 r180 top
TP37 "TP_SM_1MM" TP_SM_1MM 3149.61,2598.43 r90 top
TP38 "TP_SM_1MM" TP_SM_1MM 2102.36,1401.57 r90 top
TP39 "TP_SM_1MM" TP_SM_1MM 3149.61,2440.94 r180 top
TP40 "TP_SM_1MM" TP_SM_1MM 3149.61,2519.68 r180 top
TP41 "TP_SM_1MM" TP_SM_1MM 3692.63,4586.61 r180 top
TP42 "TP_SM_1MM" TP_SM_1MM 3444.88,1240.16 r90 top
TP43 "TP_SM_1MM" TP_SM_1MM 3444.88,1318.9 r180 top
TP44 "TP_SM_1MM" TP_SM_1MM 3444.88,1437.01 r90 top
TP45 "TP_SM_1MM" TP_SM_1MM 3972.44,1215.07 r90 top
TP46 "TP_SM_1MM" TP_SM_1MM 3809.06,1125.98 r90 top
TP47 "TP_SM_1MM" TP_SM_1MM 3972.44,1125.98 r90 top
TP48 "TP_SM_1MM" TP_SM_1MM 3809.06,1215.07 r90 top
TP49 "TP_SM_1MM" TP_SM_1MM 1320.95,1692.91 r90 top
TP50 "TP_SM_1MM" TP_SM_1MM 3864.32,1851.39 r90 top
TP51 "TP_SM_1MM" TP_SM_1MM 807.09,2481.3 r90 top
TP52 "TP_SM_1MM" TP_SM_1MM 3149.61,3657.48 r90 top
TP53 "TP_SM_1MM" TP_SM_1MM 4330.71,1742.13 r180 top
TP54 "TP_SM_1MM" TP_SM_1MM 3809.06,1358.27 r270 top
TP55 "TP_SM_1MM" TP_SM_1MM 4330.71,1318.9 r270 top
TP56 "TP_SM_1MM" TP_SM_1MM 3809.06,1437.01 r180 top
TP57 "TP_SM_1MM" TP_SM_1MM 3864.31,1759.24 r0 top
TP58 "5011" Keystone5011 2566.93,3220.47 r0 top
U1 "TPS259470ARPWR" RPW0010A-MFG 1053.15,708.66 r0 top
U2 "TVS1401DRBR" DRB0008A 915.35,492.13 r180 top
U3 "TPS563211DRLR" DRL0008A 1033.46,2253.94 r180 top
U4 "TPS563211DRLR" DRL0008A 1029.53,1299.21 r180 top
U5 "TPS65130RGER" RGE0024B 1850.24,1870.27 r270 top
U6 "TPS7A3901DSCR" DSC0010J 1811.02,1053.15 r270 top
U7 "MSPM0G3507SPM" PM0064A-MFG 2125.98,2814.96 r90 top
U8 "SN74LVC1G125DBVR" DBV0005A_N 1279.53,3228.35 r0 top
U9 "IS31CG5317-LQLS3" FP-IS31CG5317-LQLS3_LQFP80-MFG 2578.74,4370.08 r0 top
U10 "TLV1805DBVR" DBV0006A_N 3631.89,4277.56 r270 top
U11 "TS12A4515DBVR" DBV0005A_N 4143.7,3602.36 r90 top
U12 "TS12A4515DBVR" DBV0005A_N 4301.18,3602.36 r90 top
U13 "TLV9151IDBVR" DBV0005A-MFG 4458.66,3602.36 r90 top
U14 "TPS281C100BDNTR" DNT0012B-MFG 4346.46,3009.84 r180 top
U15 "TLV7011DCKR" DCK0005A_N 3464.57,3051.18 r180 top
U16 "DRV8220DSGR" DSG0008A-MFG 4458.66,2236.22 r180 top
U17 "TL431AQDBVR" DBV0005A_N 3750,2352.36 r90 top
U18 "TLV7011DCKR" DCK0005A_N 4015.75,2391.73 r180 top
U19 "THVD2429DRCR" DRC0010V-MFG 3395.67,885.83 r270 top
U20 "TRSF3221EIRGTR" RGT0016C-MFG 3927.17,905.51 r180 top
U21 "TCAN1044AVDDFRQ1" DDF0008A-MFG 2992.13,1446.85 r270 top
U22 "ESD2CAN24DBZR" DBZ0003A-MFG 2992.13,748.03 r90 top
U23 "TCAN1044AVDDFRQ1" DDF0008A-MFG 2618.11,1437.01 r270 top
U24 "ESD2CAN24DBZR" DBZ0003A-MFG 2618.11,738.19 r90 top
U25 "SN74LVC1G17DBVR" DBV0005A_N 4271.65,1604.33 r180 top
U26 "TPL7407LPWR" PW0016A_L 4458.66,1043.31 r0 top
U27 "SN74LVC1G17DBVR" DBV0005A_N 4271.65,1456.69 r180 top
U28 "TLV9001IDBV" DBV0005A_N 3769.69,1614.17 r180 top
U29 "MSP432E401YTPDT" PDT0128A 1358.27,4360.24 r90 top
U30 "ESDS314DBVR" DBV0005A_N 1751.97,3956.69 r180 top
U31 "ESDS314DBVR" DBV0005A_N 1909.45,3574.8 r90 top
U32 "TPD2E001DRLR" DRL0005A 925.2,4852.36 r180 top
U33 "TPD2E001DRLR" DRL0005A 2618.11,1683.07 r180 top
U34 "TPD2E001DRLR" DRL0005A 1785.17,5024.69 r270 top
U35 "ESDS314DBVR" DBV0005A_N 2312.99,826.77 r180 top
Y1 "830103622909" FP-830103622909_SMT_CRYSTAL_3MM4_2MM7-MFG 2027.56,3208.66 r180 top
Y2 "ABM8W-25.0000MHZ-8-D1X-T3" FP-ABM8W-25.0000MHZ-8-D1X-T3_SMD4-MFG 3228.35,4251.97 r90 top
Y3 "NX3225GA-16.000M-STD-CRG-1" NDK_NX3225GA 1161.42,4832.68 r270 top
ZZ2 "These assemblies are ESD sensitive, ESD precautions shall be observed." AssemblyNote 224.37,7510.22 r0 top
ZZ3 "These assemblies must be clean and free from flux and all contaminants. Use of no clean flux is not acceptable." AssemblyNote 224.37,7421.66 r0 top
ZZ4 "These assemblies must comply with workmanship standards IPC-A-610 Class 2, unless otherwise specified." AssemblyNote 224.37,7333.1 r0 top

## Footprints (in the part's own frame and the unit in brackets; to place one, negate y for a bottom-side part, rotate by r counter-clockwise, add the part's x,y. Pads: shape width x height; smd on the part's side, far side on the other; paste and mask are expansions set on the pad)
0402 [mm] "0402 from SM-752 data"
  rect 0.8x0.6 smd: 1(-0.6,0) 2(0.6,0)
  silkscreen extent -1.22,-0.52 1.22,0.52, body extent -0.55,-0.3 0.55,0.3, height 0.6
0402S [mil] "Based on C0402S footprint from PADS legacy"
  rect 15x24 smd: 1(-20,0) 2(20,0)
  body extent -22,-12 22,12, height 24
0603 [mm] "0603 from SM-752 data"
  rect 1x0.95 smd: 1(-0.8,0) 2(0.8,0)
  silkscreen extent -1.52,-0.69 1.52,0.69, body extent -0.87,-0.47 0.87,0.47, height 1
0805_HV [mil] "0805 with 30mil clearance between pads"
  rect 50x63 smd: 1(-40,0) 2(40,0)
  silkscreen extent -74,-40 74,40, body extent -43,-29 43,29, height 57
1206 [mm] "1206 from SM-752 data"
  rect 1.3x1.85 smd: 1(-1.45,0) 2(1.45,0)
  silkscreen extent -2.4,-1.21 2.4,1.21, body extent -1.7,-0.9 1.7,0.9, height 1.35
1206_180 [mm] "1206_180"
  rect 1.1x1.6 smd: 1(-1.7,0) 2(1.7,0)
  silkscreen extent -0.9,-1 0.9,1, body extent -1.75,-0.95 1.75,0.95, height 1.8
1210_270 [mm] "1210"
  rect 1.3x2.7 smd: 1(-1.45,0) 2(1.45,0)
  silkscreen extent -2.32,-1.57 2.32,1.57, body extent -1.7,-1.35 1.7,1.35, height 2.7
2512 [mm] "Chip Resistor, Body 6.3x3.2mm, IPC Medium Density"
  rect 1.3x3.4 smd: 1(-2.95,0) 2(2.95,0)
  silkscreen extent -1.9,-1.6 1.9,1.6, body extent -3.22,-1.67 3.22,1.67, height 0.71
AssemblyNote [mil] "Assembly Note"
CE_Mark_5mm [mil] "Minimum text height for CE Mark"
  silkscreen extent -138,-98 138,98
DBV0005A-MFG [mm]
  rrect17% 1.1x0.6 smd paste+0 mask+0: 1(-1.3,0.95) 2(-1.3,0) 3(-1.3,-0.95) 4(1.3,-0.95) 5(1.3,0.95)
  silkscreen extent -2.57,-1.53 0.87,1.53, body extent -1.95,-1.78 1.95,1.78, height 0.25
DBV0005A_N [mm] "SOT23, 5-Leads, Body 2.9x1.6mm, Pitch 0.95mm, Lead Span 2.8mm, IPC Medium Density"
  rrect17% 1x0.6 smd: 1(-1.375,0.95) 2(-1.375,0) 3(-1.375,-0.95) 4(1.375,-0.95) 5(1.375,0.95)
  silkscreen extent -0.25,-1.55 0.25,1.55, body extent -1.42,-1.46 1.42,1.46, height 1.09
DBV0006A_N [mm] "SOT23, 6-Leads, Body 2.9x1.6mm, Pitch 0.95mm, Lead Span 2.8mm, IPC Medium Density"
  rrect17% 1x0.6 smd: 1(-1.375,0.95) 2(-1.375,0) 3(-1.375,-0.95) 4(1.375,-0.95) 5(1.375,0) 6(1.375,0.95)
  silkscreen extent -1.68,-1.55 0.5,1.55, body extent -1.42,-1.46 1.42,1.46, height 1.12
DBZ0003A-MFG [mm]
  rrect17% 1.3x0.6 smd paste+0 mask+0: 1(-1.05,0.95) 2(-1.05,-0.95) 3(1.05,0)
  silkscreen extent -0.7,-1.52 0.7,1.52, body extent -1.8,-1.62 1.8,1.62, height 0.25
DCK0005A_N [mm] "SOT353, 5-Leads, Body 2x1.3mm, Pitch 0.65mm, Lead Span 2.1mm, IPC Medium Density"
  rrect25% 0.85x0.4 smd: 1(-1.125,0.65) 2(-1.125,0) 3(-1.125,-0.65) 4(1.125,-0.65) 5(1.125,0.65)
  silkscreen extent -1.48,-1.02 0.55,1.1, body extent -1.14,-1 1.14,1, height 0.95
DDF0008A-MFG [mm]
  rrect22% 1.05x0.45 smd paste+0 mask+0: 1(-1.3,0.975) 2(-1.3,0.325) 3(-1.3,-0.325) 4(-1.3,-0.975) 5(1.3,-0.975) 6(1.3,-0.325) 7(1.3,0.325) 8(1.3,0.975)
  silkscreen extent -1.67,-1.48 0.4,1.83, body extent -1.92,-1.73 1.92,1.73, height 0.25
